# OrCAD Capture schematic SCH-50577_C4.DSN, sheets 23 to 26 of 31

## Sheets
23 25 MCU-Link: size D
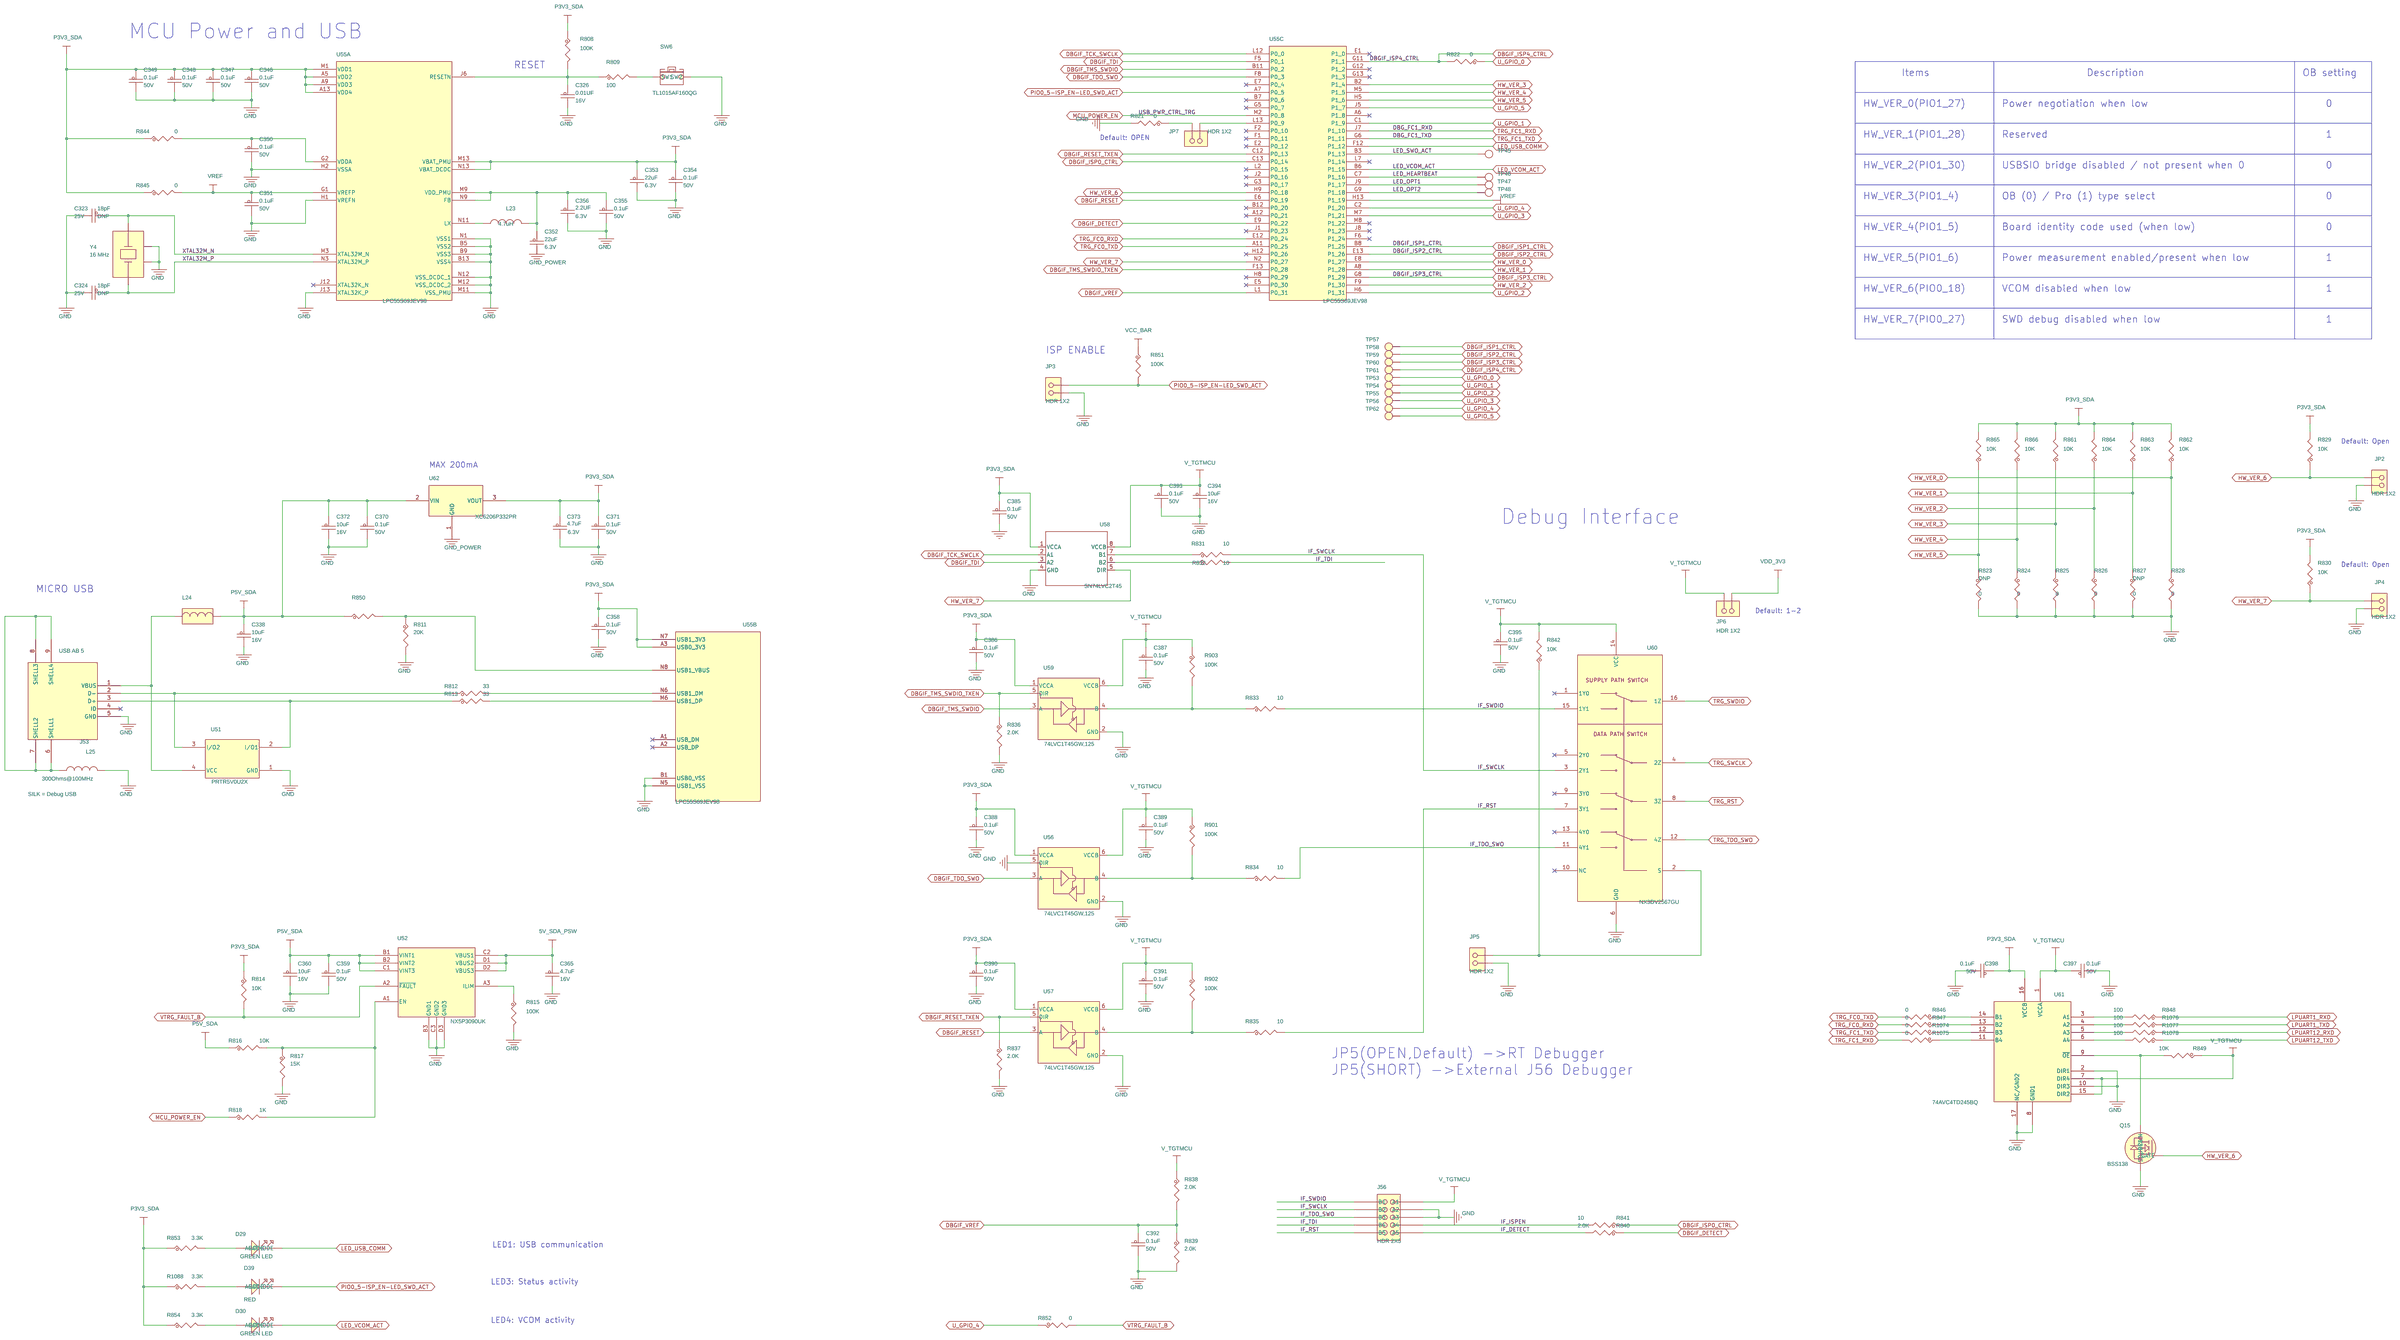
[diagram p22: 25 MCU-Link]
24 27 Audio Extension: size C
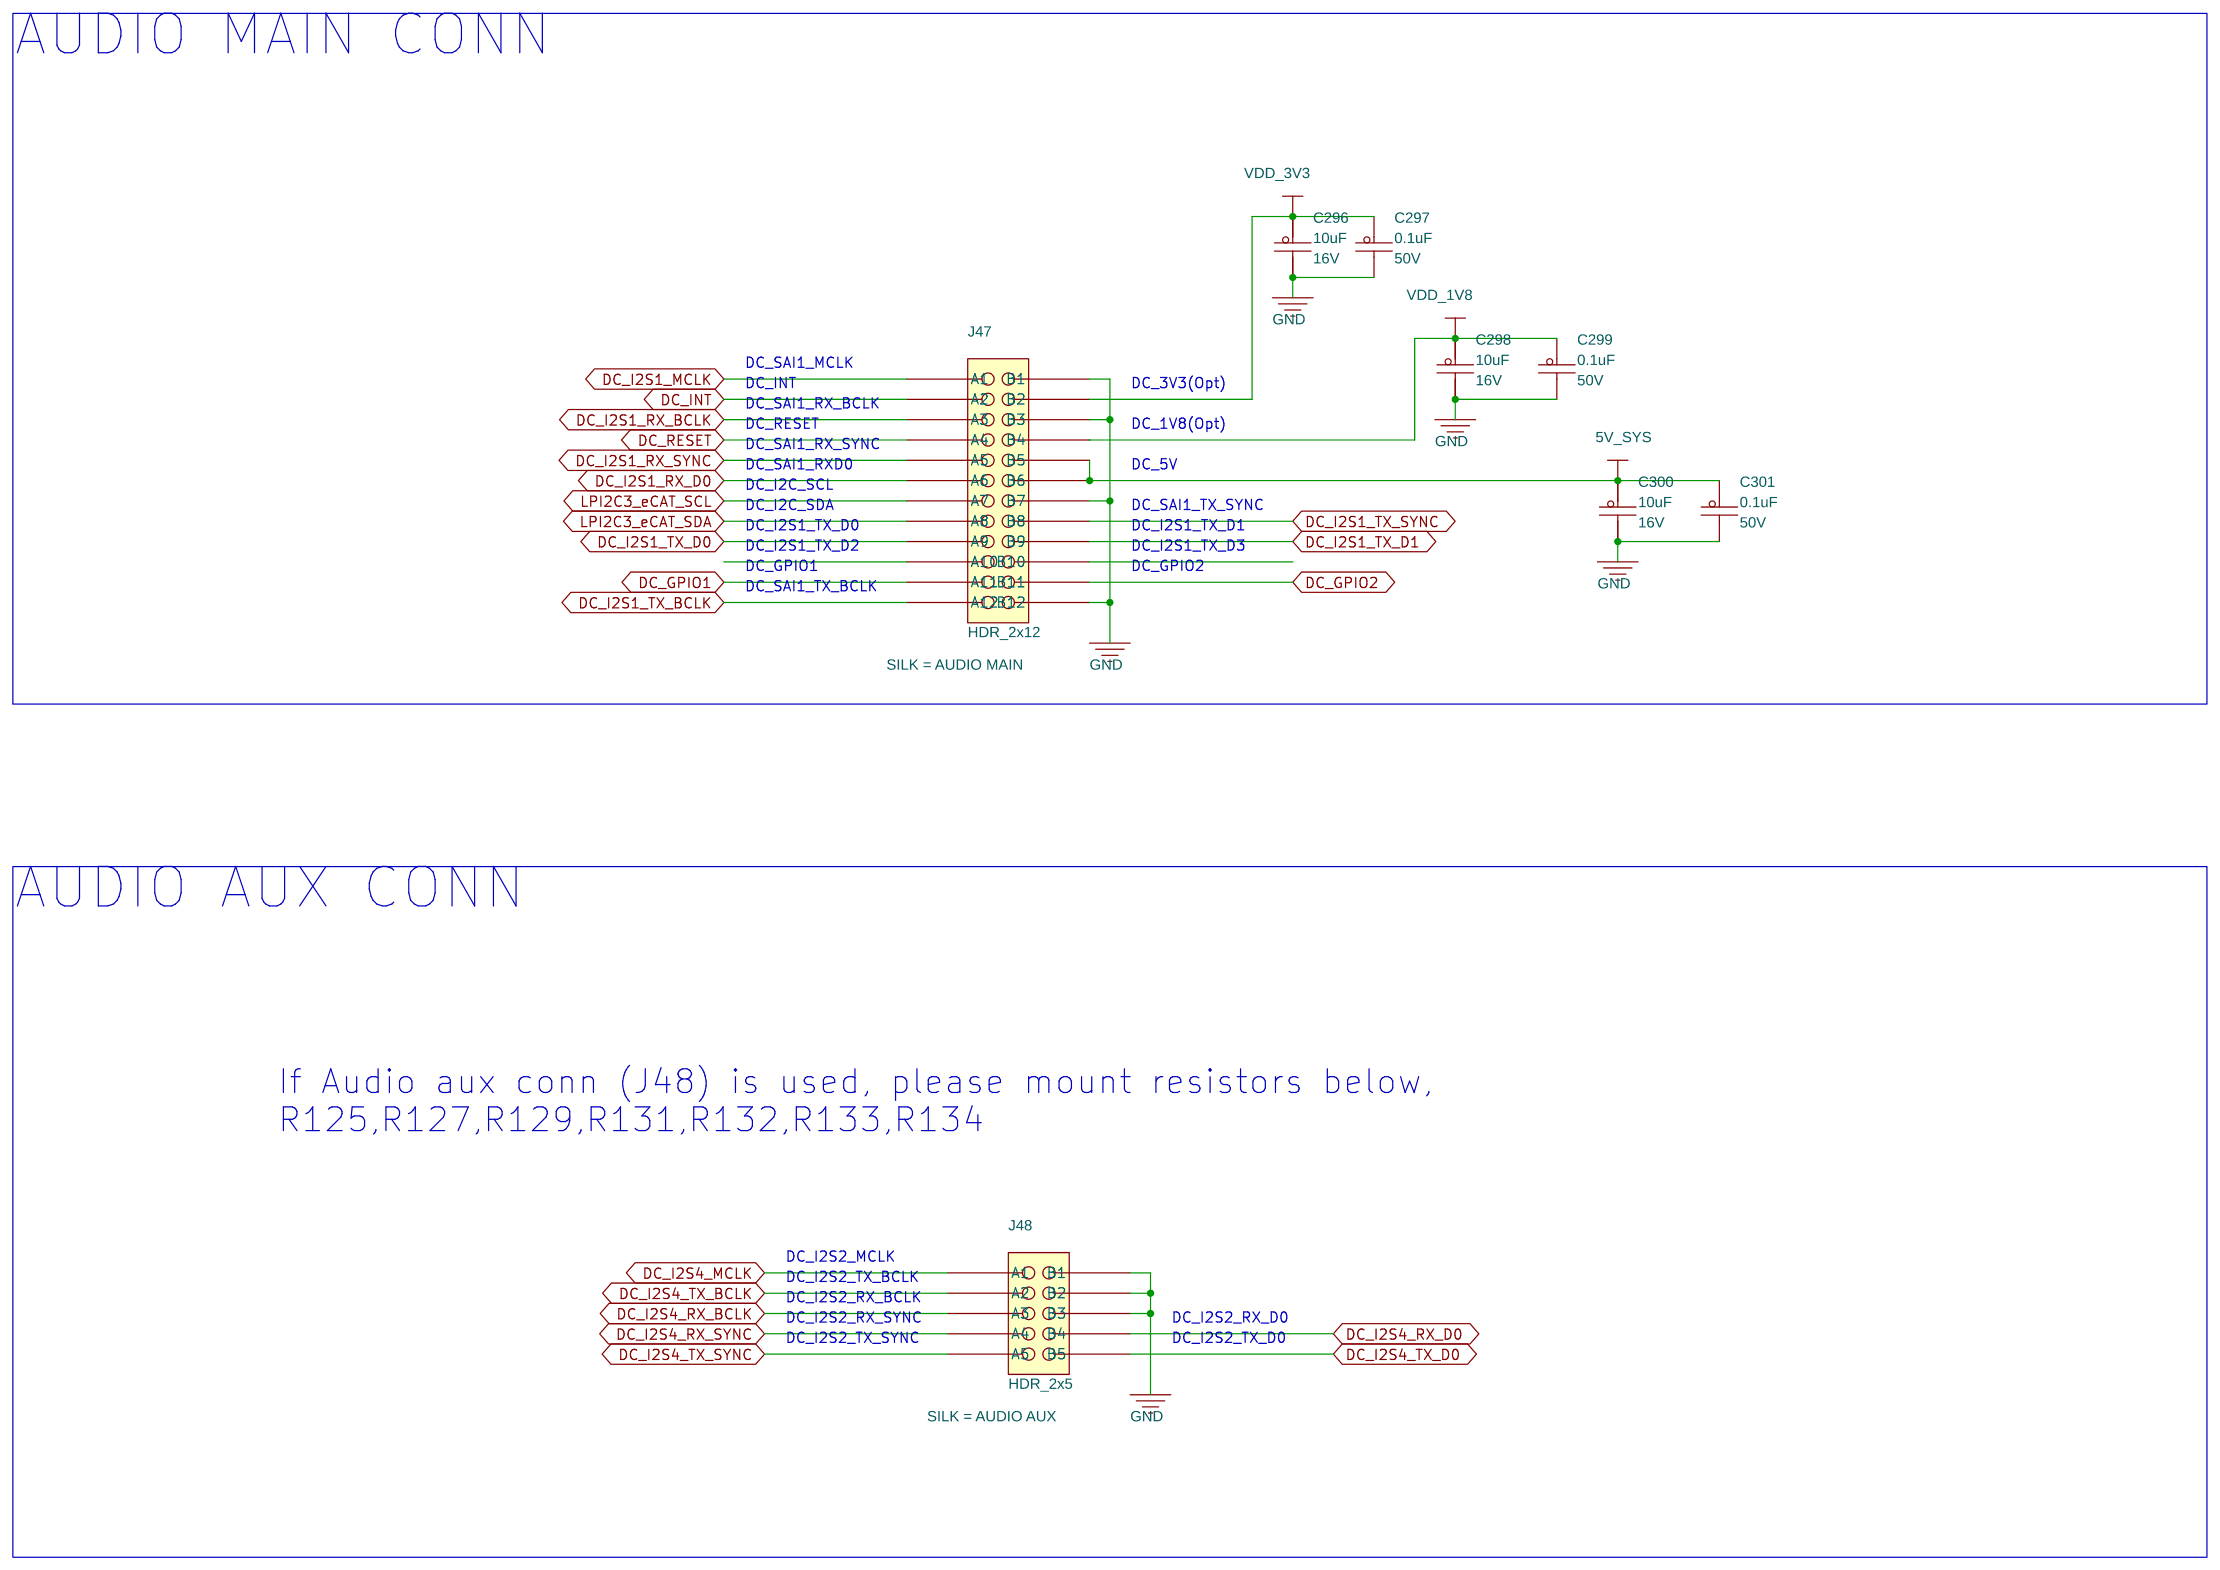
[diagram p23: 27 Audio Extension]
25 28 SINC&I3C: size C
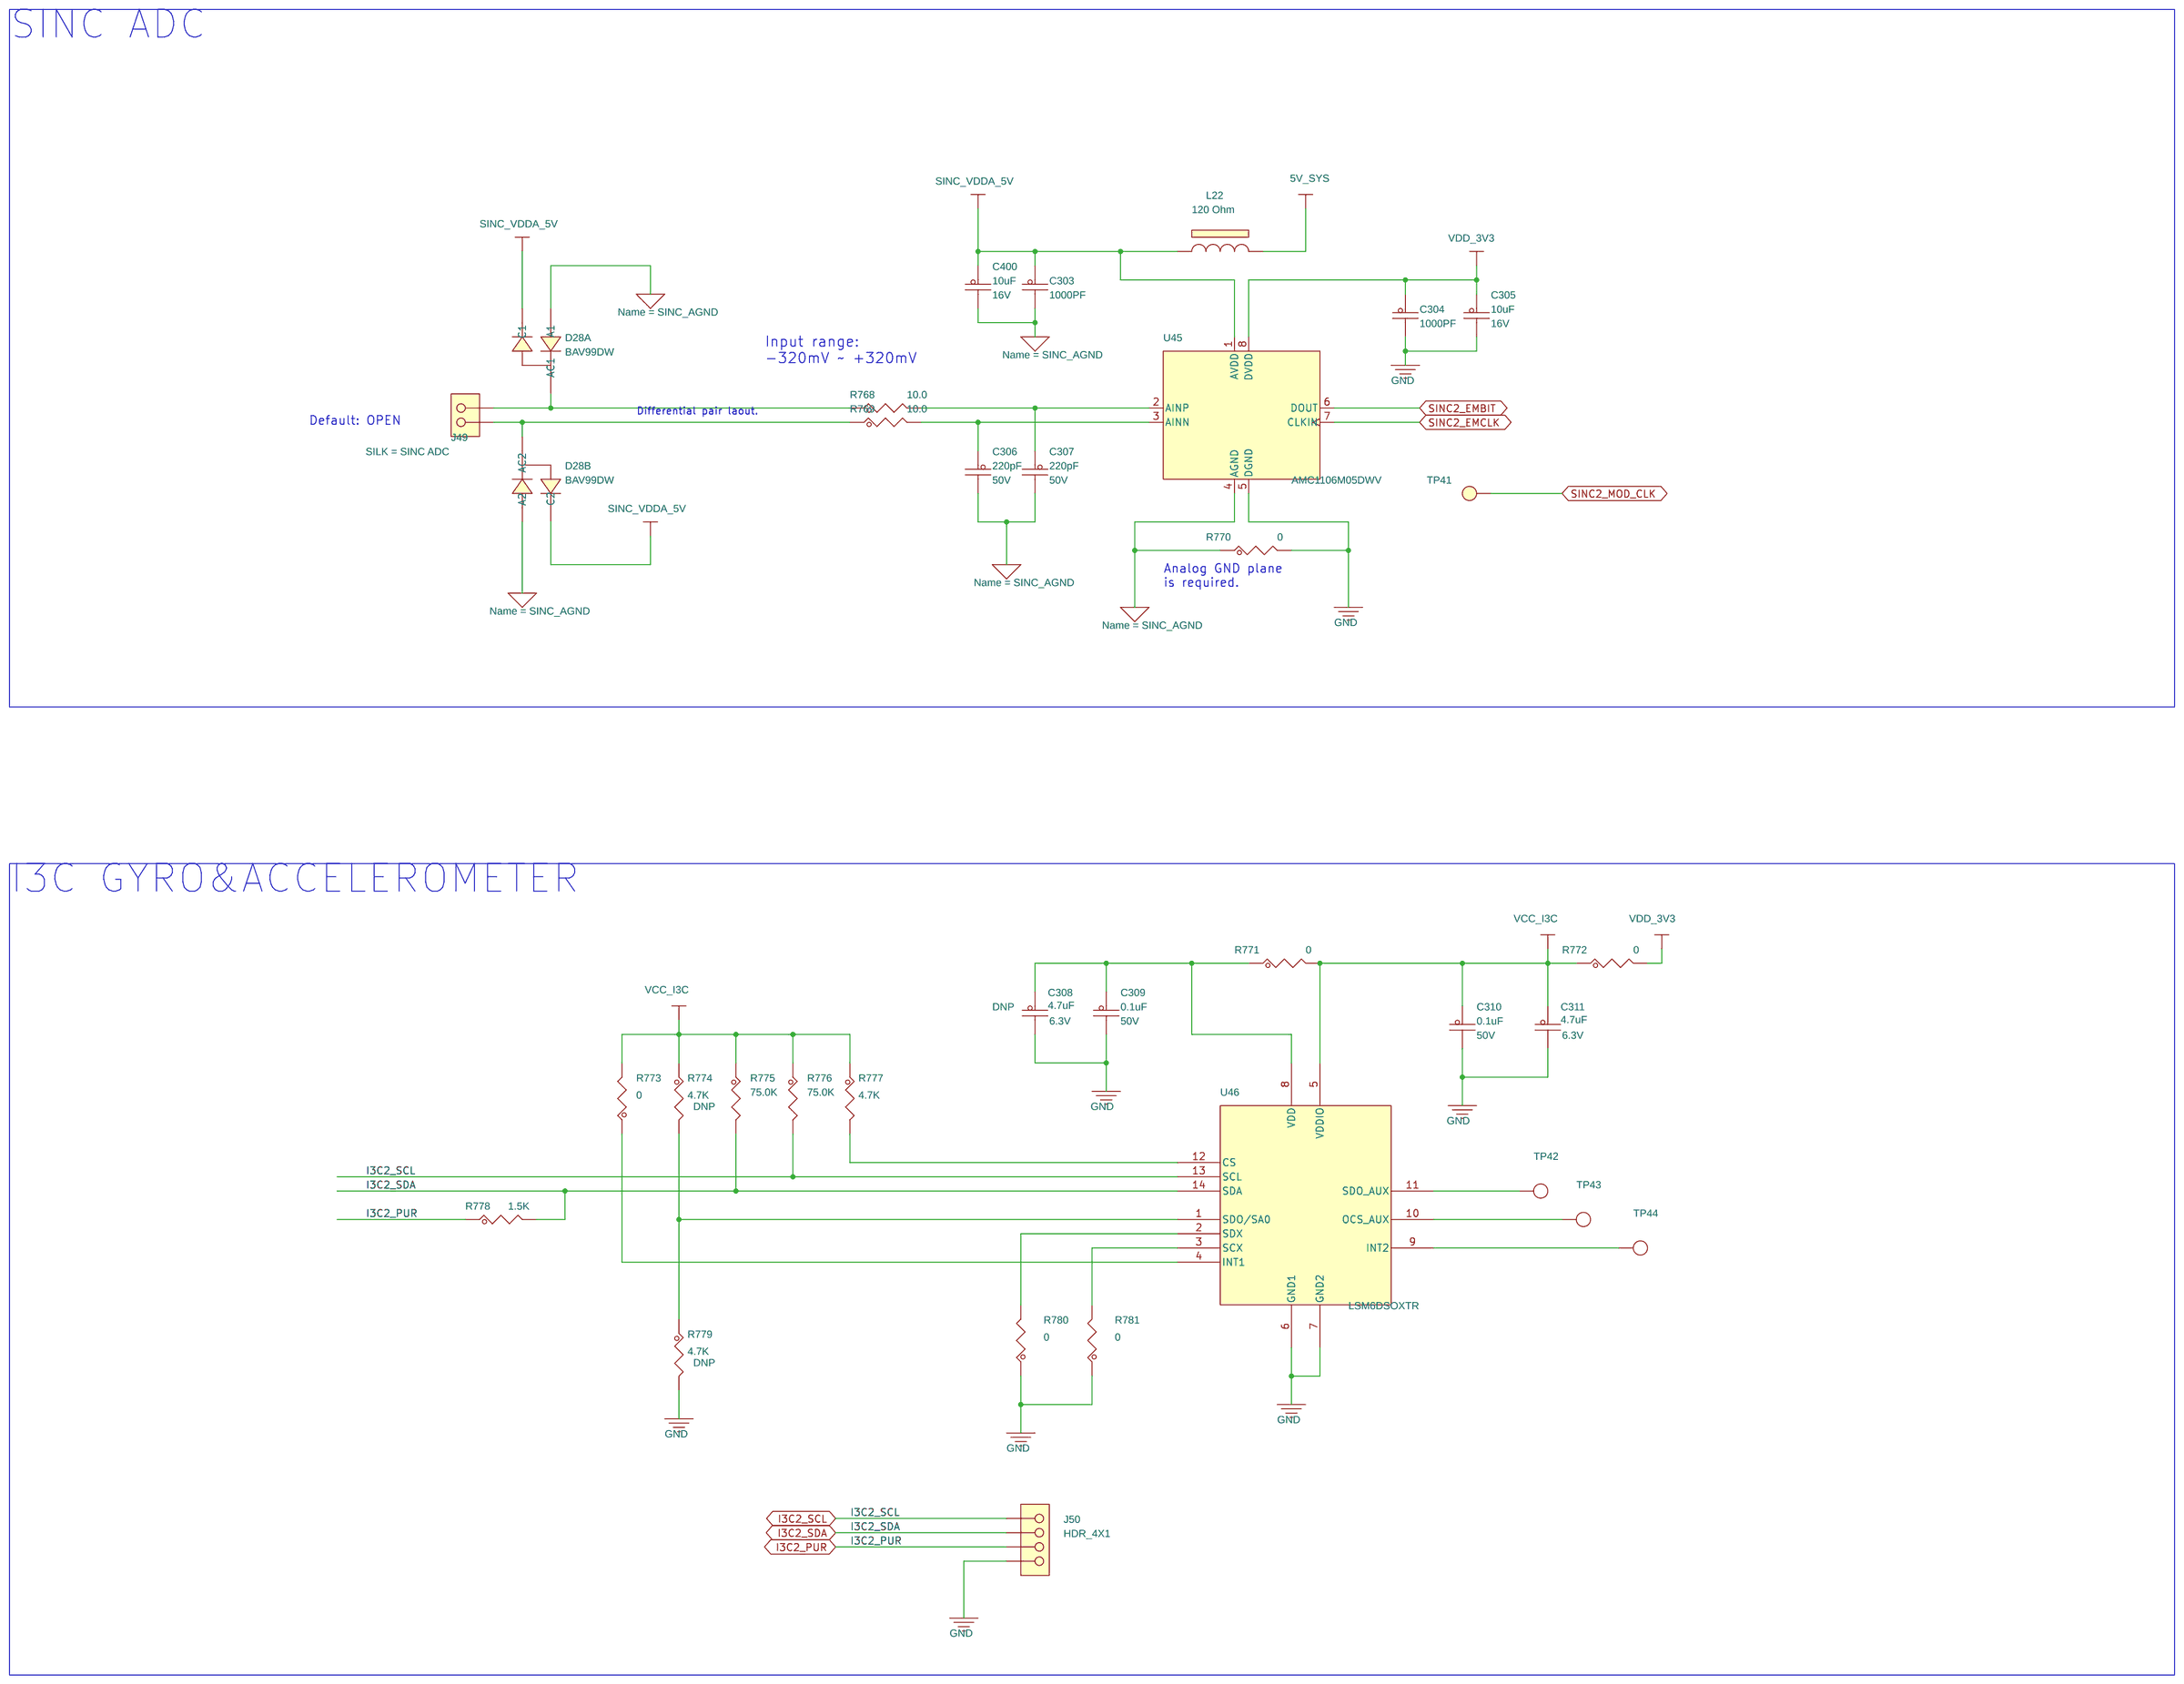
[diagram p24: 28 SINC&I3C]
26 30 MISC: size C
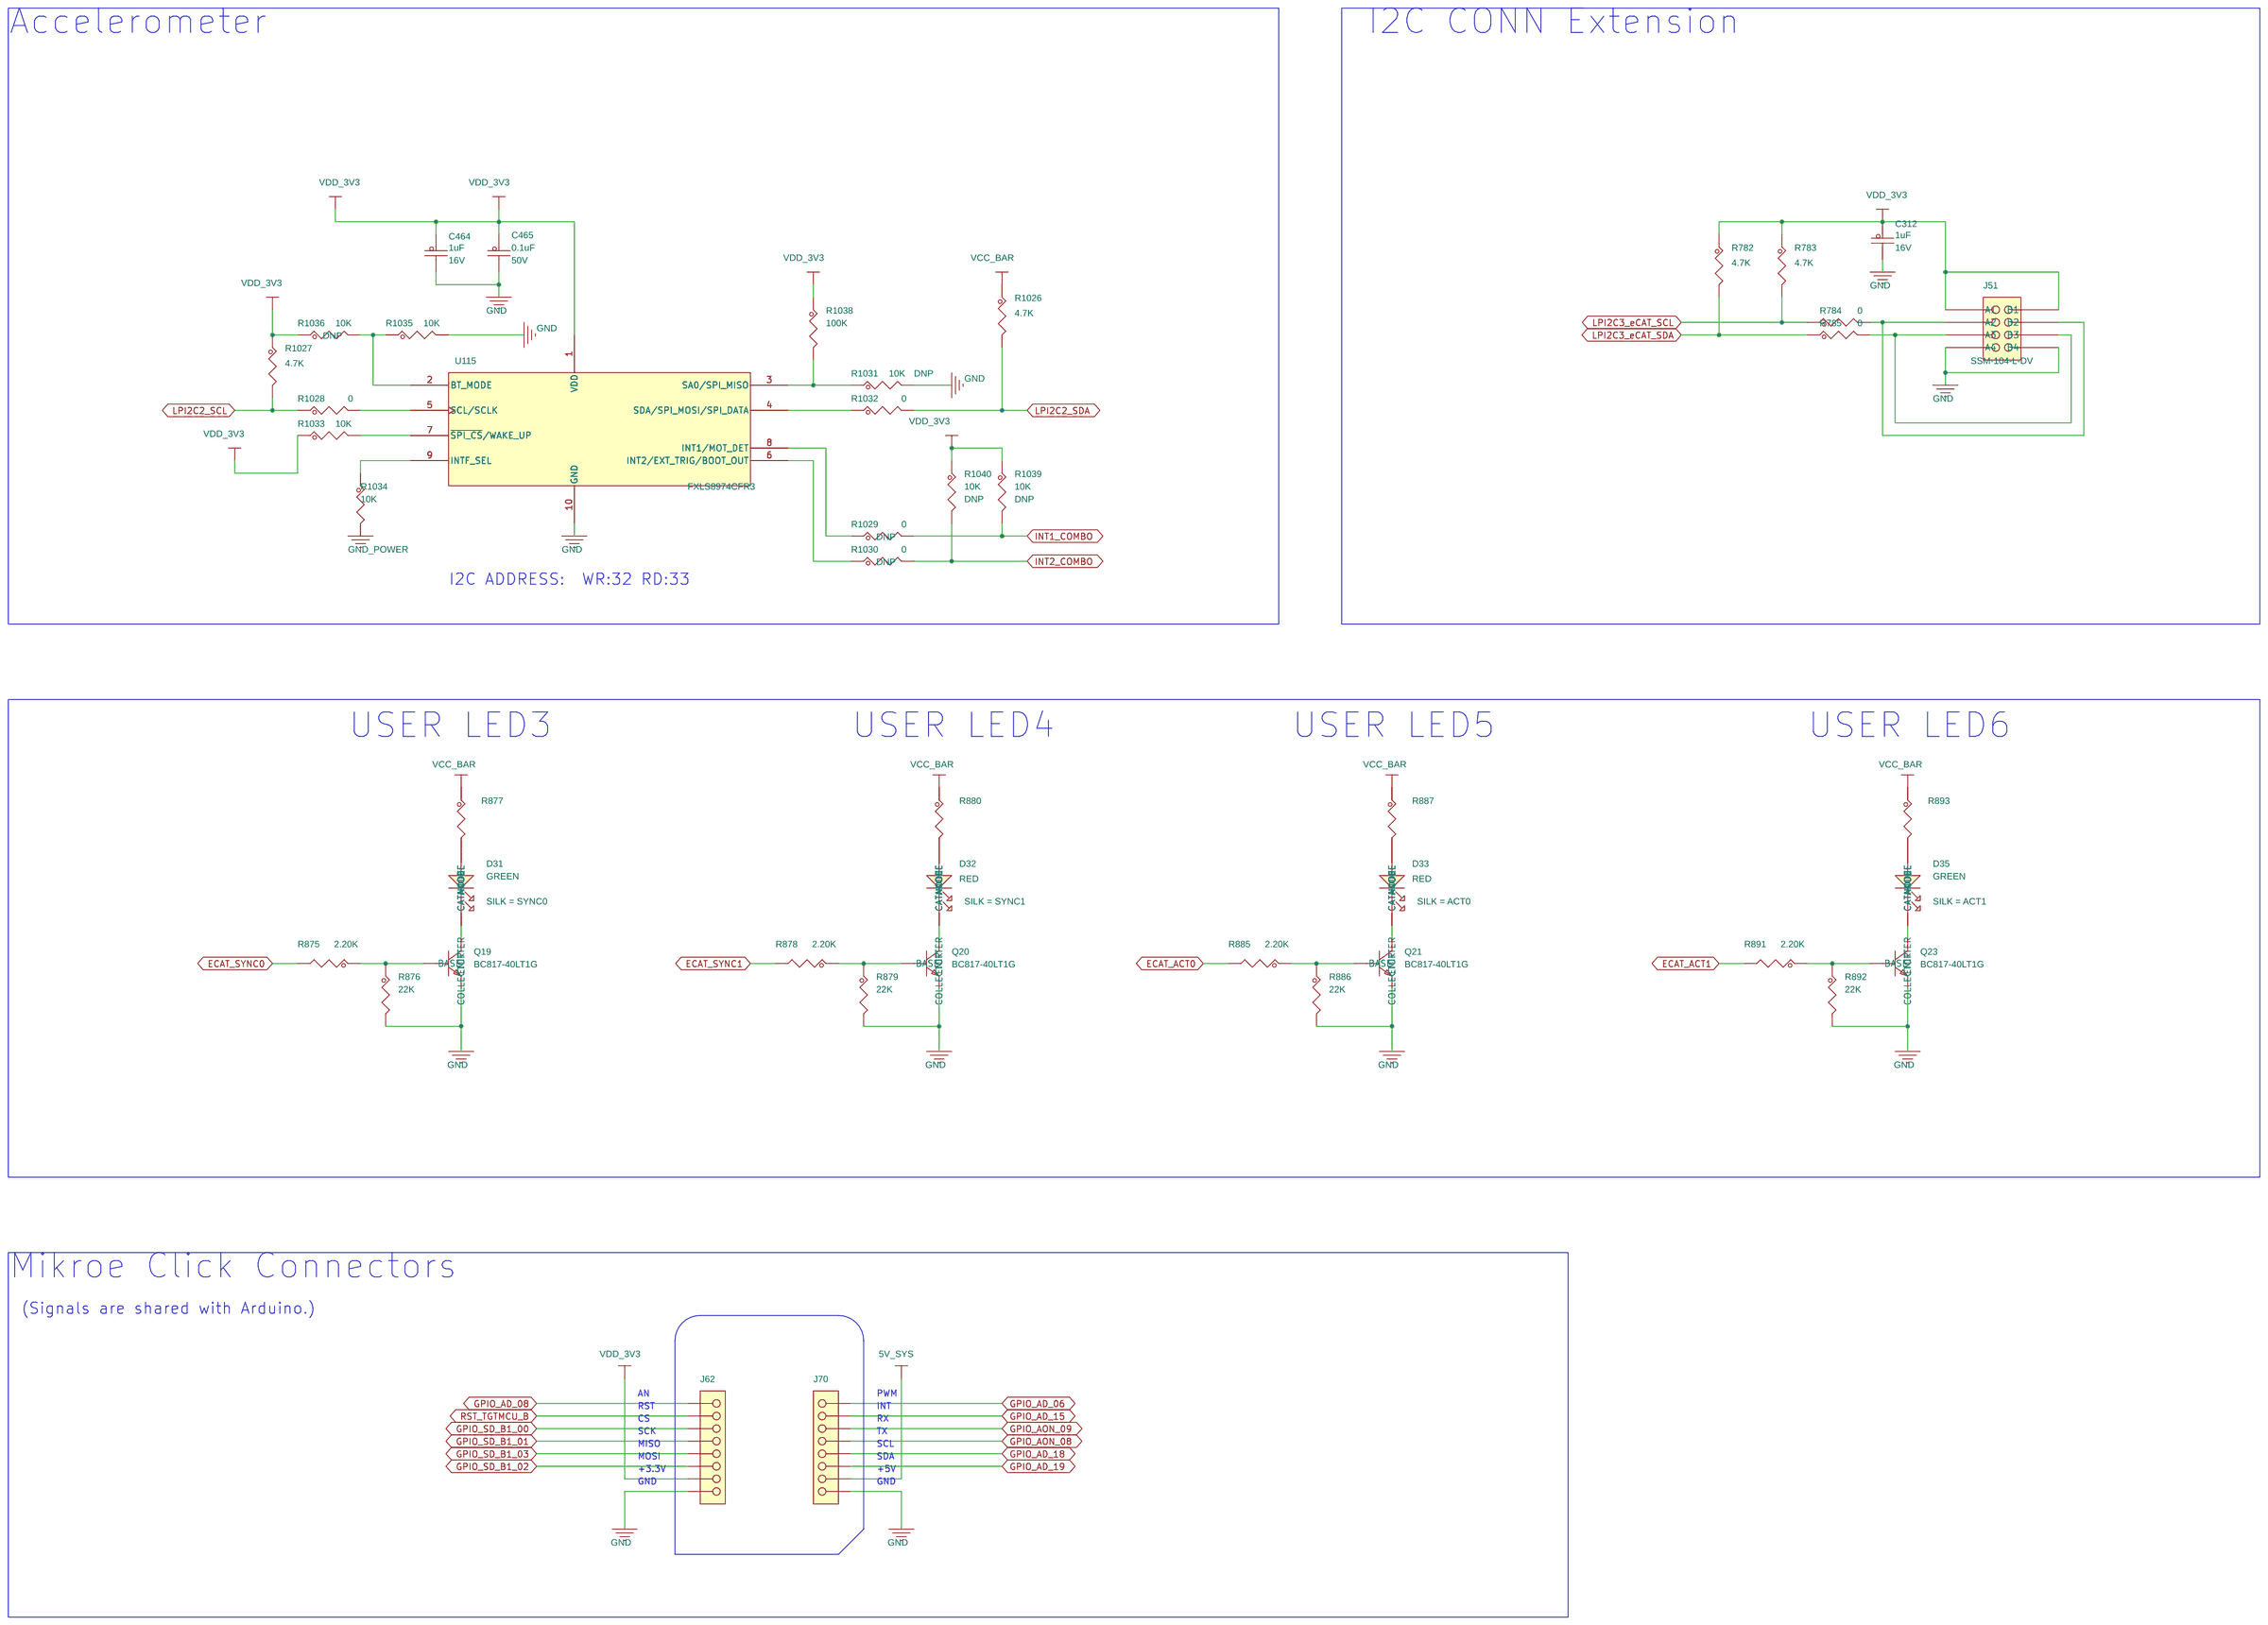
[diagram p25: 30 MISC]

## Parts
sheet 25 MCU-Link
C323  18pF  [0402_CC]
C324  18pF  [0402_CC]
C326  0.01UF  [0402_CC]
C338  10uF  [CC0603_OV]
C346  0.1uF  [0402_CC]
C347  0.1uF  [0402_CC]
C348  0.1uF  [0402_CC]
C349  0.1uF  [0402_CC]
C350  0.1uF  [0402_CC]
C351  0.1uF  [0402_CC]
C352  22uF  [CC0603_OV]
C353  22uF  [CC0603_OV]
C354  0.1uF  [0402_CC]
C355  0.1uF  [0402_CC]
C356  2.2UF  [0402_CC]
C358  0.1uF  [0402_CC]
C359  0.1uF  [0402_CC]
C360  10uF  [CC0603_OV]
C365  4.7uF  [CC0603_OV]
C370  0.1uF  [0402_CC]
C371  0.1uF  [0402_CC]
C372  10uF  [CC0603_OV]
C373  4.7uF  [cc0402_tol0p15]
C385  0.1uF  [0402_CC]
C386  0.1uF  [0402_CC]
C387  0.1uF  [0402_CC]
C388  0.1uF  [0402_CC]
C389  0.1uF  [0402_CC]
C390  0.1uF  [0402_CC]
C391  0.1uF  [0402_CC]
C392  0.1uF  [0402_CC]
C393  0.1uF  [0402_CC]
C394  10uF  [CC0603_OV]
C395  0.1uF  [0402_CC]
C397  0.1uF  [0402_CC]
C398  0.1uF  [0402_CC]
D29  GREEN LED  [LED_0603]
D30  GREEN LED  [LED_0603]
D39  RED  [LED_0603]
J53  USB AB 5  [con9_microAB_usb_shell_th]
J56  HDR 2X5  [con2x5_50_th_a]
JP2  HDR 1X2  [HDR102]
JP3  HDR 1X2  [HDR102]
JP4  HDR 1X2  [HDR102]
JP5  HDR 1X2  [HDR102]
JP6  HDR 1X2  [HDR102]
JP7  HDR 1X2  [HDR102]
L23  4.7uH  [IND_0805]
L24  330 OHM  [IND_0805]
L25  300Ohms@100MHz  [ind_1p8x1mm_sm]
Q15  BSS138  [sot23_a]
R808  100K  [0402_CC]
R809  100  [0402_CC]
R811  20K  [0402_CC]
R812  33  [0402_CC]
R813  33  [0402_CC]
R814  10K  [0402_CC]
R815  100K  [0402_CC]
R816  10K  [0402_CC]
R817  15K  [0402_CC]
R818  1K  [0402_CC]
R821  0  [0402_CC]
R822  0  [0402_CC]
R823  0  [0402_CC]
R824  0  [0402_CC]
R825  0  [0402_CC]
R826  0  [0402_CC]
R827  0  [0402_CC]
R828  0  [0402_CC]
R829  10K  [0402_CC]
R830  10K  [0402_CC]
R831  10  [0402_CC]
R832  10  [0402_CC]
R833  10  [0402_CC]
R834  10  [0402_CC]
R835  10  [0402_CC]
R836  2.0K  [0402_CC]
R837  2.0K  [0402_CC]
R838  2.0K  [0402_CC]
R839  2.0K  [0402_CC]
R840  2.0K  [0402_CC]
R841  10  [0402_CC]
R842  10K  [0402_CC]
R844  0  [0402_CC]
R845  0  [0402_CC]
R846  0  [0402_CC]
R847  0  [0402_CC]
R848  100  [0402_CC]
R849  10K  [0402_CC]
R850  10K  [0402_CC]
R851  100K  [0402_CC]
R852  0  [0402_CC]
R853  3.3K  [0402_CC]
R854  3.3K  [0402_CC]
R861  10K  [0402_CC]
R862  10K  [0402_CC]
R863  10K  [0402_CC]
R864  10K  [0402_CC]
R865  10K  [0402_CC]
R866  10K  [0402_CC]
R901  100K  [0402_CC]
R902  100K  [0402_CC]
R903  100K  [0402_CC]
R1074  0  [0402_CC]
R1075  0  [0402_CC]
R1076  100  [0402_CC]
R1077  100  [0402_CC]
R1078  100  [0402_CC]
R1088  3.3K  [0402_CC]
SW6  TL1015AF160QG  [sw2_spst_4x3_sm_f]
TP45  TPAD_030  [TPAD_030]
TP46  TPAD_030  [TPAD_030]
TP47  TPAD_030  [TPAD_030]
TP48  TPAD_030  [TPAD_030]
TP53  TP_35MIL  [testpoint_35mil]
TP54  TP_35MIL  [testpoint_35mil]
TP55  TP_35MIL  [testpoint_35mil]
TP56  TP_35MIL  [testpoint_35mil]
TP57  TP_35MIL  [testpoint_35mil]
TP58  TP_35MIL  [testpoint_35mil]
TP59  TP_35MIL  [testpoint_35mil]
TP60  TP_35MIL  [testpoint_35mil]
TP61  TP_35MIL  [testpoint_35mil]
TP62  TP_35MIL  [testpoint_35mil]
U51  PRTR5V0U2X  [SOT143B]
U52  NX5P3090UK  [wlcsp12_0p4_1p38x1p68mm_smdp]
U55  LPC55S69JEV98  [bga98_0p5_7x7]  (sections A,B,C)
U56  74LVC1T45GW,125  [SOT-363_0P65_SMT]
U57  74LVC1T45GW,125  [SOT-363_0P65_SMT]
U58  SN74LVC2T45  [SSOP8_DCU]
U59  74LVC1T45GW,125  [SOT-363_0P65_SMT]
U60  NX3DV2567GU  [pqfn16_0p4_2p65x1p85]
U61  74AVC4TD245BQ  [dhvqfn16_0p5_3p6x2p6]
U62  XC6206P332PR  [sot89_123_a]
Y4  16 MHz  [xtlosc4_2p6x2p1mm_sm]
sheet 27 Audio Extension
C296  10uF  [CC0603_OV]
C297  0.1uF  [0402_CC]
C298  10uF  [CC0603_OV]
C299  0.1uF  [0402_CC]
C300  10uF  [CC0603_OV]
C301  0.1uF  [0402_CC]
J47  HDR_2x12  [hdr2x12_2mm_th]
J48  HDR_2x5  [hdr2x5_2mm_th]
sheet 28 SINC&I3C
C303  1000PF  [0402_CC]
C304  1000PF  [0402_CC]
C305  10uF  [CC0603_OV]
C306  220pF  [0402_CC]
C307  220pF  [0402_CC]
C308  4.7uF  [cc0402_tol0p15]
C309  0.1uF  [0402_CC]
C310  0.1uF  [0402_CC]
C311  4.7uF  [cc0402_tol0p15]
C400  10uF  [CC0603_OV]
D28  BAV99DW  [sc70-6]  (sections A,B)
J49  HDR 1X2  [HDR102]
J50  HDR_4X1  [HDR104_STAG_TSM_SM]
L22  120 Ohm  [0402_CC]
R768  10.0  [0402_CC]
R769  10.0  [0402_CC]
R770  0  [0402_CC]
R771  0  [0402_CC]
R772  0  [0402_CC]
R773  0  [0402_CC]
R774  4.7K  [0402_CC]
R775  75.0K  [RC0402_25]
R776  75.0K  [RC0402_25]
R777  4.7K  [0402_CC]
R778  1.5K  [RC0402_25]
R779  4.7K  [0402_CC]
R780  0  [0402_CC]
R781  0  [0402_CC]
TP41  TP_35MIL  [testpoint_35mil]
TP42  TEST POINT  [tp_th_018]
TP43  TEST POINT  [tp_th_018]
TP44  TEST POINT  [tp_th_018]
U45  AMC1106M05DWV  [soic8_1p27_7p6x5p95mm]
U46  LSM6DSOXTR  [lga14_0p5_3x2p5]
sheet 30 MISC
C312  1uF  [0402_CC]
C464  1uF  [0402_CC]
C465  0.1uF  [0402_CC]
D31  GREEN  [LED_0603]
D32  RED  [LED_0603]
D33  RED  [LED_0603]
D35  GREEN  [LED_0603]
J51  SSM-104-L-DV  [con_2x4_skt_100_sm]
J62  SKT_1X8  [con_1x8_skt_2p54_th]
J70  SKT_1X8  [con_1x8_skt_2p54_th]
Q19  BC817-40LT1G  [SOT23]
Q20  BC817-40LT1G  [SOT23]
Q21  BC817-40LT1G  [SOT23]
Q23  BC817-40LT1G  [SOT23]
R782  4.7K  [0402_CC]
R783  4.7K  [0402_CC]
R784  0  [0402_CC]
R785  0  [0402_CC]
R875  2.20K  [RC0603_OV]
R876  22K  [0402_CC]
R877  220  [RC0603_OV]
R878  2.20K  [RC0603_OV]
R879  22K  [0402_CC]
R880  220  [RC0603_OV]
R885  2.20K  [RC0603_OV]
R886  22K  [0402_CC]
R887  220  [RC0603_OV]
R891  2.20K  [RC0603_OV]
R892  22K  [0402_CC]
R893  220  [RC0603_OV]
R1026  4.7K  [0402_CC]
R1027  4.7K  [0402_CC]
R1028  0  [0402_CC]
R1029  0  [0402_CC]
R1030  0  [0402_CC]
R1031  10K  [0402_CC]
R1032  0  [0402_CC]
R1033  10K  [0402_CC]
R1034  10K  [0402_CC]
R1035  10K  [0402_CC]
R1036  10K  [0402_CC]
R1038  100K  [0402_CC]
R1039  10K  [0402_CC]
R1040  10K  [0402_CC]
U115  FXLS8974CFR3  [DFN_10_0P4_2X2]

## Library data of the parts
C323 C324 = CAP_NP: CAP CER 18pF 25V 5% C0G 0402; AGILE_PN: 150-78760; ASSY_OPT: DNP; CAD_APPROVED: Yes; FPLIST: CC0402_25,CC0402_HD,0402_CC; HEIGHT: 0.56MM; MFG_NAME01: AVX; MFG_PN01: 04023A180JAT2A; ROHS: Yes; TOL: 5%; Tolerance: 5%; VOLTAGE: 25V
C326 = CAP_NP: CAP CER 0.01UF 16V 20% X7R 0402; AGILE_PN: 150-30082; CAD_APPROVED: Yes; FPLIST: CC0402_25,CC0402_HD,0402_CC; HEIGHT: 0.56MM; MFG_NAME01: AVX; MFG_PN01: 0402YC103MAT2A; Package Size: 0402; ROHS: Yes; TOL: 20%; Tolerance: 20%; VOLTAGE: 16V
C296 C298 C300 C305 C338 C360 C372 C394 C400 = CAP_NP: CAP CER 10uF 16V 20% X6S AEC-Q200 0603; AGILE_PN: 150-80530; CAD_APPROVED: Yes; FPLIST: CC0603_OV,CC0603,0603_CC_NSP; HEIGHT: 1MM; MFG_NAME01: MURATA; MFG_PN01: GRT188C81C106ME13D; Package Size: 0603; ROHS: Yes; Temp Range: -55°C to 105°C; Tolerance: 10%; VOLTAGE: 16V
C297 C299 C301 C309 C310 C346-C351 C354 C355 C358 C359 C370 C371 C385-C393 C395 C397 C398 C465 = CAP_NP: CAP CER 0.1uF 50V 10% X7R AEC-Q200 0402; AGILE_PN: 150-79461; CAD_APPROVED: Yes; FPLIST: CC0402_25,CC0402_HD,0402_CC,CC0402_18,capc0402_l; HEIGHT: 0.55MM; MFG_NAME01: MURATA; MFG_PN01: GCM155R71H104KE02D; Package Size: 0402; ROHS: Yes; Tolerance: 10%; VOLTAGE: 50V
C352 C353 = CAP_NP: CAP CER 22uF 6.3V 20% X6S 0603; AGILE_PN: 150-79717; CAD_APPROVED: Yes; FPLIST: CC0603_OV,CC0603,0603_CC_NSP; HEIGHT: 1MM; MFG_NAME01: MURATA; MFG_PN01: GRM188C80J226ME15D; Package Size: 0603; Package Type: 180mm ReelPAPER W8P4; ROHS: Yes; Tolerance: 20%; VOLTAGE: 6.3V
C356 = CAP_NP: CAP CER 2.2UF 6.3V 10% X6S 0402; AGILE_PN: 150-80139; CAD_APPROVED: Yes; FPLIST: CC0402_25,CC0402_HD,0402_CC,capc0402_l; HEIGHT: 0.55MM; MFG_NAME01: MURATA; MFG_PN01: GRM155C80J225KE95D; ROHS: Yes; Temp Range: -55 to 105&#8451;; VOLTAGE: 6.3V
C365 = CAP_NP: CAP CER 4.7uF 16V 10% X7R 0603; AGILE_PN: 150-80123; CAD_APPROVED: Yes; FPLIST: CC0603_OV,CC0603,0603_cc_tol,cc0603_0805_nsp; HEIGHT: 1MM; MFG_NAME01: MURATA; MFG_PN01: GRM188Z71C475KE21; Package Size: 0603; ROHS: Yes; Temp Range: -55°C ~ 125°C; Tolerance: 10%; VOLTAGE: 16V
C311 C373 = CAP_NP: CAP CER 4.7uF 6.3V 20% X6S 0402; AGILE_PN: 150-81296; CAD_APPROVED: Yes; FPLIST: cc0402_tol0p15,cc0402_tol0p15_ov,cc0402_25_tol0p2,0402_cc_nsp; HEIGHT: 0.65MM; MFG_NAME01: MURATA; MFG_PN01: GRM155C80J475MEAA; Package Size: 0402 (1005 Metric); Package Type: SMD/SMT; ROHS: Yes; Rated Voltage: 6.3V; Temp Range: -55°C to +105°C; Tolerance: 20%; VOLTAGE: 6.3V
D29 D30 = LED: LED GRN SGL 20MA SMT 0603; AGILE_PN: 370-75904; CAD_APPROVED: Yes; HEIGHT: 0.65MM; MFG_NAME01: VISHAY INTERTECHNOLOGY; MFG_PN01: TLMG1100-GS08; VOLTAGE: 3V
D39 = LED: LED ULTRA BRIGHT RED SGL 30MA 0603; AGILE_PN: 370-75079; CAD_APPROVED: Yes; HEIGHT: 0.9MM; MFG_NAME01: LITE ON; MFG_PN01: LTST-C190KRKT; ROHS: Yes; Rated Voltage: 2V; Temp Range: -30° C to + 85° C; Temp_Range: -30° C to + 85° C; VOLTAGE: 2V
J53 = MICRO_USB_CONN_9PIN: CON 5 USB MICRO-AB RA SKT SMT 0.65MM SP AU; 3D_Mechanical_Footprint_File: ftp://fcl.am.freescale.net/ALLEGRO/step/con9_microAB_usb_shell_th.STEP; AGILE_PN: 211-78692; CAD_APPROVED: Yes; HEIGHT: 2.8MM; MFG_NAME01: HIROSE; MFG_PN01: ZX62D-AB-5P8(30); ROHS: Yes; SILK: Debug USB
J56 = CONN_HDR_5X2: HDR 2X5 TH 50MIL CTR 222H AU 90L; 3D_Mechanical_Footprint_File: ftp://fcl.am.freescale.net/ALLEGRO/step/con2x5_50_th_a.STEP; AGILE_PN: 210-82391; CAD_APPROVED: Yes; HEIGHT: 5.65MM; MFG_NAME01: WURTH ELEKTRONIK EISOS GMBH & CO. KG (ELECTRONIC & ELECTROMEHANICAL COMP); MFG_PN01: 62201021121; ROHS: Yes; Temp Range: -40C to +105C
JP2-JP5 JP7 = CONN_HDR_2X1: HDR 1X2 TH 100MIL SP 339H AU 98L; AGILE_PN: 210-81490; CAD_APPROVED: Yes; FPLIST: HDR102,SH_HDR102_BOTTOM; HEIGHT: 8.59MM; MFG_NAME01: ANYTRONIC CORPORATION LIMITED; MFG_PN01: 0901S0202011N9T-31RF; ROHS: Yes; Temp Range: -55°C to +105°C; Temp_Range: -55°C to +105°C
JP6 = CONN_HDR_2X1: HDR 1X2 TH 100MIL SP 339H AU 98L; AGILE_PN: 210-81490; CAD_APPROVED: Yes; FPLIST: HDR102,SH_HDR102_BOTTOM; HEIGHT: 8.59MM; Jumper(Default): 1-2; MFG_NAME01: ANYTRONIC CORPORATION LIMITED; MFG_PN01: 0901S0202011N9T-31RF; ROHS: Yes; Temp Range: -55°C to +105°C; Temp_Range: -55°C to +105°C
L23 = INDUCTOR: IND -- 4.7uH@1MHZ 800mA 20% 0805; AGILE_PN: 180-79181; CAD_APPROVED: yes; HEIGHT: 1MM; MFG_NAME01: Murata Electronics; MFG_PN01: LQM21PN4R7MGRD; Package Size: 0805 (2012 Metric); ROHS: Yes
L24 = BEAD: IND FER BEAD 330OHM@100MHZ 2.5A -- SMT; 3D_Mechanical_Footprint_File: ftp://fcl.am.freescale.net/ALLEGRO/step/ind_0805.STEP; AGILE_PN: 180-30021; CAD_APPROVED: YES; HEIGHT: 1.05 MM; MFG_NAME01: TDK; MFG_PN01: MPZ2012S331AT000; PART_TYPE: FERRITE; ROHS: Yes; Temp Range: -55°C to +125°C; Tolerance: 25%
L25 = INDUCTOR: IND FER BEAD 300Ohms@100MHz 2A 25% 0603; AGILE_PN: 180-78959; CAD_APPROVED: Yes; HEIGHT: 1MM; MFG_NAME01: WURTH ELEKTRONIK EISOS GMBH & CO. KG (ELECTRONIC & ELECTROMEHANICAL COMP); MFG_PN01: 742792641; Package Size: 0603; ROHS: Yes; Temp Range: -55°C to 125°C
Q15 = NMOS_3P_A: TRAN NMOS PWR 200mA 50V AEC-Q101 SOT23; AGILE_PN: 480-80247; CAD_APPROVED: Yes; HEIGHT: 1.1MM; MFG_NAME01: DIODES INC; MFG_PN01: BSS138Q-7-F; ROHS: Yes; Temp Range: -55C to +150C
R808 R815 R851 = RES: RES MF 100K 1/16W 5% AEC-Q200 0402; AGILE_PN: 470-82056; CAD_APPROVED: Yes; HEIGHT: 0.4MM; MFG_NAME01: VISHAY INTERTECHNOLOGY; MFG_PN01: CRCW0402100KJNED; ROHS: Yes; Temp Range: -55C to +155C; Tolerance: 5%; VOLTAGE: 50V
R809 = RES: RES MF 100 OHM 1/16W 5% 0402; AGILE_PN: 470-82143; CAD_APPROVED: Yes; HEIGHT: 0.45MM; MFG_NAME01: YAGEO AMERICA; MFG_PN01: RC0402JR-07100RL; ROHS: Yes; Temp Range: -55°C to +155°C; Tolerance: 5%
R811 = RES: RES MF 20K 1/16W 5% 0402; AGILE_PN: 470-76086; CAD_APPROVED: Yes; HEIGHT: 0.4 MM; MFG_NAME01: YAGEO AMERICA; MFG_PN01: RC0402JR-0720KL; ROHS: Yes; Tolerance: 5%
R812 R813 = RES: RES MF 33 OHM 1/16W 5% 0402; AGILE_PN: 470-75634; CAD_APPROVED: Yes; HEIGHT: 0.41mm; MFG_NAME01: SMEC; MFG_PN01: RC73L2Z330JTF; ROHS: Yes; Tolerance: 5%
R814 R816 R829 R830 R842 R849 R861-R866 = RES: RES MF 10K 1/16W 5% 0402; AGILE_PN: 470-75557; CAD_APPROVED: Yes; HEIGHT: 0.4 MM; MFG_NAME01: VISHAY INTERTECHNOLOGY; MFG_PN01: CRCW040210K0JNED; ROHS: Yes; Tolerance: 5%
R817 = RES: RES MF 15K 1/16W 5% 0402; AGILE_PN: 470-30313; CAD_APPROVED: Yes; FPLIST: RC0402_25,RC0402_HD,0402_CC; HEIGHT: 0.45 MM; MFG_NAME01: VISHAY INTERTECHNOLOGY; MFG_PN01: CRCW040215K0JNED; ROHS: Yes; Tolerance: 5%; VOLTAGE: 1/16W
R818 = RES: RES MF 1.0K 1/16W 5% 0402; AGILE_PN: 470-75555; CAD_APPROVED: Yes; HEIGHT: 0.41mm; MFG_NAME01: VISHAY INTERTECHNOLOGY; MFG_PN01: CRCW04021K00JNED; ROHS: Yes; Tolerance: 5%
R821 R822 R824-R826 R828 R846 R847 R852 R1074 R1075 = RES: RES MF ZERO OHM 1/16W 5% 0402; AGILE_PN: 470-75394; CAD_APPROVED: Yes; FPLIST: RC0402_25,RC0402_HD,RC0402_X2,0402_CC; HEIGHT: 0.45 MM; MFG_NAME01: YAGEO AMERICA; MFG_PN01: RC0402JR-070RL; ROHS: Yes; SIGNAL_MODEL: DEFAULT_RESISTOR_33.000000OHM_2_1; TOL: 5%; Tolerance: 5%; VOLTAGE: 1/16W
R823 R827 = RES: RES MF ZERO OHM 1/16W 5% 0402; AGILE_PN: 470-75394; ASSY_OPT: DNP; CAD_APPROVED: Yes; FPLIST: RC0402_25,RC0402_HD,RC0402_X2,0402_CC; HEIGHT: 0.45 MM; MFG_NAME01: YAGEO AMERICA; MFG_PN01: RC0402JR-070RL; ROHS: Yes; SIGNAL_MODEL: DEFAULT_RESISTOR_33.000000OHM_2_1; TOL: 5%; Tolerance: 5%; VOLTAGE: 1/16W
R831-R835 R841 = RES: RES MF 10 OHM 1/16W 1% AEC-Q200 0402; AGILE_PN: 470-80978; CAD_APPROVED: Yes; FPLIST: RC0402_25,RC0402_HD,0402_CC; HEIGHT: 0.4MM; MFG_NAME01: KOA SPEER; MFG_PN01: RK73H1ETTP10R0F; ROHS: Yes; Temp Range: –55 °C to +155 °C; Tolerance: 1%
R836-R840 = RES: RES MF 2.0K 1/16W 5% 0402; AGILE_PN: 470-75638; CAD_APPROVED: Yes; FPLIST: RC0402_25,RC0402_HD,0402_CC; HEIGHT: 0.45MM; MFG_NAME01: SMEC; MFG_PN01: RC73L2Z202JTF; ROHS: Yes; Tolerance: 5%; VOLTAGE: 1/16W
R770-R773 R780 R781 R844 R845 = RES: RES MF ZERO OHM 1/16W 5% 0402; AGILE_PN: 470-75394; CAD_APPROVED: Yes; FPLIST: RC0402_25,RC0402_HD,RC0402_X2,0402_CC; HEIGHT: 0.45 MM; MFG_NAME01: ROHM; MFG_PN01: MCR01MZPJ000; ROHS: Yes; Tolerance: 5%; VOLTAGE: 1/16W
R848 R1076-R1078 = RES: RES MF 100 OHM 1/16W 5% AEC-Q200 0402; AGILE_PN: 470-80555; CAD_APPROVED: Yes; FPLIST: RC0402_25,RC0402_HD,RC0402_X2,0402_CC; HEIGHT: 0.45mm; MFG_NAME01: VISHAY INTERTECHNOLOGY; MFG_PN01: CRCW0402100RJNED; ROHS: Yes
R850 = RES: RES MF 10K 1/16W 5% 0402; AGILE_PN: 470-75557; CAD_APPROVED: Yes; FPLIST: RC0402_25,RC0402_HD,0402_CC; HEIGHT: 0.4 MM; MFG_NAME01: VISHAY INTERTECHNOLOGY; MFG_PN01: CRCW040210K0JNED; ROHS: Yes; TOL: 5%; Tolerance: 5%
R853 R854 R1088 = RES: RES MF 3.3K 1/16W 5% 0402; AGILE_PN: 470-76064; CAD_APPROVED: Yes; FPLIST: RC0402_25,RC0402_HD,0402_CC; HEIGHT: 0.40 MM; MFG_NAME01: YAGEO AMERICA; MFG_PN01: RC0402JR-073K3L; ROHS: Yes; Tolerance: 5%; VOLTAGE: 1/16W
R901-R903 = RES: RES MF 100K 1/16W 1% 0402; AGILE_PN: 470-76240; CAD_APPROVED: Yes; FPLIST: RC0402_25,RC0402_HD,0402_CC; HEIGHT: 0.4MM; MFG_NAME01: NIC COMPONENTS CORP; MFG_PN01: NRCL04F1003TRF; ROHS: Yes; Tolerance: 1%
SW6 = SW2P_SPST: SW SPST PB 50MA 12V SMT; AGILE_PN: 510-77720; CAD_APPROVED: Yes; FPLIST: sw2_spst_4x3_sm,sw2_spst_4x3_sm_f; HEIGHT: 2.4MM; MFG_NAME01: E SWITCH; ROHS: Yes
TP45-TP48 = TESTLOOP: TEST POINT PAD 30MIL DIA SMT, NO PART TO ORDER; 3D_Mechanical_Footprint_File: ftp://fcl.am.freescale.net/ALLEGRO/step/tpad_030.STEP; AGILE_PN: 211-76642; CAD_APPROVED: Yes; HEIGHT: 0.1MM; MFG_NAME01: NOTACOMPONENT; MFG_PN01: NOTACOMPONENT; ROHS: Yes
TP41 TP53-TP62 = T_POINT_R: TEST POINT PAD .035 SMT, no part to order; AGILE_PN: 510-75618; CAD_APPROVED: Yes; HEIGHT: 0.1MM; ROHS: Yes
U51 = PRTR5V0U2X: IC USB ESD PROTECTION 8KV SOT143; AGILE_PN: 315-76725; CAD_APPROVED: Yes; HEIGHT: 1.1MM; MFG_NAME01: NEXPERIA; MFG_PN01: PRTR5V0U2X,215; ROHS: Yes; Temp Range: -40° C to +85° C; VOLTAGE: 5.0V
U52 = NX5P3090UK_WLCSP12: IC USB PD TYPE C CURRENT LIMITED PWR SW 2.5-5.5V WLCSP12; AGILE_PN: 312-81574; CAD_APPROVED: Yes; HEIGHT: 0.565 MM; MFG_NAME01: NXP SEMICONDUCTORS; MFG_PN01: NX5P3090UK,012; ROHS: Yes
U55 = NIOBE4_MINI_FBGA98: IC MCU ARM FLASH 640KB SRAM 320KB 1.8-3.6V VFBGA 98; AGILE_PN: 344-02410; CAD_APPROVED: Yes; FPLIST: bga98_0p5_7x7,bga98_0p5_7x7_c010s_nsp; HEIGHT: 0.97 MM; MFG_NAME01: NXP SEMICONDUCTORS; ROHS: Yes; Supply Voltage: 1.8-3.6V; Temp Range: -40 to +105C; VOLTAGE: 1.8/3.6V
U56 U57 U59 = 74LVCH1T45_6P: IC XCVR XLATING DUAL 3-STATE 1.2- 5.5V TSSOP6; AGILE_PN: 312-81277; CAD_APPROVED: Yes; HEIGHT: 1.1MM; MFG_NAME01: NEXPERIA; ROHS: Yes; VOLTAGE: 1.2- 5.5V
U58 = SN74LVC2T45DCUT_8P: IC XCVR DUAL BIT 1.65-5.5V VSSOP8; AGILE_PN: 312-80349; CAD_APPROVED: Yes; HEIGHT: 0.9MM; MFG_NAME01: TEXAS INSTRUMENTS; MFG_PN01: SN74LVC2T45DCUT; ROHS: Yes
U60 = NX3DV2567GU_XQFN_16P: IC LIN SW 4PDT 1.4-4.3V XQFN16; AGILE_PN: 315-80822; CAD_APPROVED: Yes; HEIGHT: 0.5 MM; MFG_NAME01: NXP SEMICONDUCTORS; MFG_PN01: NX3DV2567GU,115; ROHS: Yes; VOLTAGE: 1.4-4.3V
U61 = 74AVC4TD245BQ_DHVQFN16: IC DUAL SUPPLY XCVR XLTR 4BIT 0-3.6V DHVQFN16; 3D_Mechanical_Footprint_File: ftp://fcl.am.freescale.net/ALLEGRO/step/dhvqfn16_0p5_3p6x2p6.STEP; AGILE_PN: 312-81329; CAD_APPROVED: Yes; HEIGHT: 1MM; MFG_NAME01: NEXPERIA; MFG_PN01: 74AVC4TD245BQ,115; ROHS: Yes
U62 = S0T89_3P: IC VREG LDO 3.3V 200mA 1.8-6V SOT89-3; AGILE_PN: 315-81174; CAD_APPROVED: Yes; HEIGHT: 1.6MM; MFG_NAME01: TOREX; ROHS: Yes; Temp Range: -40°C to +85°C
Y4 = XTAL_13: XTAL 16MHZ -- 2520 SMD; AGILE_PN: 230-75774; CAD_APPROVED: Yes; HEIGHT: 0.55MM; MFG_NAME01: NDK; MFG_PN01: NX2520SA-16.000000MHz; ROHS: Yes
J47 = CONN_HDR_12X2: HDR 2X12 TH 2MM CTR 246H AU 110L; AGILE_PN: 210-82753; CAD_APPROVED: Yes; HEIGHT: 6.25MM; MFG_NAME01: ANYTRONIC CORPORATION LIMITED; MFG_PN01: 0912S01 12011N6T-31LF; Package Type: Through Hole; ROHS: Yes; SILK: AUDIO MAIN; Temp Range: -55 °C to 105 °C
J48 = CONN_HDR_5X2: HDR 2X5 TH 2MM CTR 246H AU 110L; AGILE_PN: 210-82754; CAD_APPROVED: Yes; HEIGHT: 6.25MM; MFG_NAME01: ANYTRONIC CORPORATION LIMITED; MFG_PN01: 0912S01 05011N6T-31LF; Package Type: Through Hole; ROHS: Yes; SILK: AUDIO AUX; Temp Range: -55C to +105C
C303 C304 = CAP_NP: CAP CER 1000PF 16V 10% X7R CC0402 ROHS; AGILE_PN: 150-75426; CAD_APPROVED: Yes; FPLIST: CC0402_25,CC0402_HD,0402_CC; HEIGHT: 0.56mm; MFG_NAME01: AVX; MFG_PN01: 0402YC102KAT2A; Package Size: 0402; ROHS: Yes; Tolerance: 10%; VOLTAGE: 16V
C306 C307 = CAP_NP: CAP CER 220PF 50V 10% X7R 0402; AGILE_PN: 150-75829; CAD_APPROVED: Yes; FPLIST: CC0402_25,CC0402_HD,0402_CC; HEIGHT: 0.55MM; MFG_NAME01: KEMET; MFG_PN01: C0402C221K5RAC; ROHS: Yes; Tolerance: 10%; VOLTAGE: 50V
C308 = CAP_NP: CAP CER 4.7uF 6.3V 20% X6S 0402; AGILE_PN: 150-81296; ASSY_OPT: DNP; CAD_APPROVED: Yes; FPLIST: cc0402_tol0p15,cc0402_tol0p15_ov,cc0402_25_tol0p2,0402_cc_nsp; HEIGHT: 0.65MM; MFG_NAME01: MURATA; MFG_PN01: GRM155C80J475MEAA; Package Size: 0402 (1005 Metric); Package Type: SMD/SMT; ROHS: Yes; Rated Voltage: 6.3V; Temp Range: -55°C to +105°C; Tolerance: 20%; VOLTAGE: 6.3V
D28 = BAV99DW: DIODE PWR SW QUAD 215MA 75V SOT363; AGILE_PN: 480-78333; CAD_APPROVED: Yes; HEIGHT: 1.1 MM; MFG_NAME01: DIODES INC; MFG_PN01: BAV99DW-7-F
J49 = CONN_HDR_2X1: HDR 1X2 TH 100MIL SP 339H AU 98L; AGILE_PN: 210-81490; CAD_APPROVED: Yes; HEIGHT: 8.59MM; MFG_NAME01: ANYTRONIC CORPORATION LIMITED; MFG_PN01: 0901S0202011N9T-31RF; ROHS: Yes; SILK: SINC ADC; Temp Range: -55°C to +105°C; Temp_Range: -55°C to +105°C
J50 = CONN_HDR_4X1: HDR 1X4 SMT 2.54MM SP 330H AU; 3D_Mechanical_Footprint_File: ftp://fcl.am.freescale.net/ALLEGRO/step/hdr104_stag_tsm_sm.STEP; AGILE_PN: 211-00001-00; CAD_APPROVED: Yes; HEIGHT: 9.65 MM; MFG_NAME01: SAMTEC; MFG_PN01: TSM-104-01-S-SV; Package Size: SMD-4; Package Type: SMD; ROHS: Yes
L22 = INDUCTOR_FERRITE: IND FER BEAD 120 OHM@100MHZ 0.5A 25% 0402; AGILE_PN: 180-77771; CAD_APPROVED: Yes; FPLIST: IND_0402,0402_CC; HEIGHT: 0.55MM; MFG_NAME01: MURATA; MFG_PN01: BLM15AG121SN1D; PART_TYPE: FERRITE\BEAD; Package Size: 0402; ROHS: Yes; Tolerance: 25%
R768 R769 = RES: RES MF 10.0 OHM 1/16W 1% 0402; AGILE_PN: 470-76090; CAD_APPROVED: Yes; FPLIST: RC0402_25,RC0402_HD,0402_CC; HEIGHT: 0.4MM; MFG_NAME01: BOURNS; MFG_PN01: CR0402-FX-10R0GLF; ROHS: Yes; Tolerance: 1%
R774 R779 = RES: RES MF 4.7K 1/16W 5% 0402; AGILE_PN: 470-75626; ASSY_OPT: DNP; CAD_APPROVED: Yes; FPLIST: RC0402_25,RC0402_HD,0402_CC; HEIGHT: 0.41mm; MFG_NAME01: NIC COMPONENTS CORP; MFG_PN01: NRCL04J472TRF; ROHS: Yes; Tolerance: 5%
R775 R776 = RES: RES MF 75.0K 1/10W 5% AEC-Q200 0402; AGILE_PN: 470-79440; CAD_APPROVED: Yes; FPLIST: RC0402_25,RC0402_HD,0402_CC; HEIGHT: 0.40MM; MFG_NAME01: KOA SPEER; MFG_PN01: RK73B1ETTP753J; ROHS: Yes; Temp Range: -55C to +155C; Tolerance: 5%; VOLTAGE: 50V
R777 R782 R783 R1026 R1027 = RES: RES MF 4.7K 1/16W 5% 0402; AGILE_PN: 470-75626; CAD_APPROVED: Yes; FPLIST: RC0402_25,RC0402_HD,0402_CC; HEIGHT: 0.41mm; MFG_NAME01: NIC COMPONENTS CORP; MFG_PN01: NRCL04J472TRF; ROHS: Yes; Tolerance: 5%
R778 = RES: RES MF 1.50K 1/10W 1% AEC-Q200 0402; AGILE_PN: 470-81990; CAD_APPROVED: Yes; FPLIST: RC0402_25,RC0402_HD,0402_CC; HEIGHT: 0.4 MM; MFG_NAME01: KOA SPEER; MFG_PN01: RK73H1ETTP1501F; ROHS: Yes; Temp Range: -55C to +155C; Tolerance: 1%; VOLTAGE: 50V
TP42-TP44 = TESTLOOP: TEST POINT PAD 036-018MIL TH, NO PART TO ORDER; AGILE_PN: 280-76691; CAD_APPROVED: Yes; HEIGHT: 0.127MM; MFG_NAME01: NA; MFG_PN01: NO PART TO ORDER1; ROHS: Yes
U45 = AMC1106_SOIC8P: IC MODULATOR DELTA-SIGMA 16BIT 3.3-5V SOIC8; 3D_Mechanical_Footprint_File: http://fcl.am.freescale.net/ALLEGRO/step/soic8_1p27_7p6x5p95mm.STEP; AGILE_PN: 315-84369; CAD_APPROVED: Yes; HEIGHT: 2.8MM; MFG_NAME01: TEXAS INSTRUMENTS; Package Size: SOIC8; ROHS: Yes; Temp Range: -40C to +125C
U46 = LSM6DSO_LGA14P: IC 3D ACCELEROMETER GYRO 1.71-3.6V LGA14; AGILE_PN: 312-82731; CAD_APPROVED: Yes; HEIGHT: 0.86MM; MFG_NAME01: ST MICROELECTRONICS; Package Size: LGA-14L; ROHS: Yes; Temp Range: -40°C to 85°C
C312 C464 = CAP_NP: CAP CER 1.0uF 16V 10% X6S 0402; AGILE_PN: 150-80262; CAD_APPROVED: Yes; FPLIST: CC0402_25,CC0402_HD,0402_CC,capc0402_l; HEIGHT: 0.55MM; MFG_NAME01: MURATA; MFG_PN01: GRM155C81C105KE11D; ROHS: Yes; Temp Range: -55°C to +105°C; Tolerance: 10%; VOLTAGE: 16V
D31 = LED: LED GRN SGL 25MA 0603; AGILE_PN: 370-76549; CAD_APPROVED: Yes; HEIGHT: 0.85MM; MFG_NAME01: KINGBRIGHT; MFG_PN01: KPT-1608SGC; ROHS: Yes; SILK: SYNC0
D32 = LED: LED ULTRA BRIGHT RED SGL 30MA 0603; AGILE_PN: 370-75079; CAD_APPROVED: Yes; HEIGHT: 0.9MM; MFG_NAME01: LITE ON; MFG_PN01: LTST-C190KRKT; ROHS: Yes; Rated Voltage: 2V; SILK: SYNC1; Temp Range: -30° C to + 85° C; Temp_Range: -30° C to + 85° C; VOLTAGE: 2V
D33 = LED: LED ULTRA BRIGHT RED SGL 30MA 0603; AGILE_PN: 370-75079; CAD_APPROVED: Yes; HEIGHT: 0.9MM; MFG_NAME01: LITE ON; MFG_PN01: LTST-C190KRKT; ROHS: Yes; Rated Voltage: 2V; SILK: ACT0; Temp Range: -30° C to + 85° C; Temp_Range: -30° C to + 85° C; VOLTAGE: 2V
D35 = LED: LED GRN SGL 25MA 0603; AGILE_PN: 370-76549; CAD_APPROVED: Yes; HEIGHT: 0.85MM; MFG_NAME01: KINGBRIGHT; MFG_PN01: KPT-1608SGC; ROHS: Yes; SILK: ACT1
J51 = CONN_HDR_4X2: CON 2X4 SKT SMT 2.54MM CTR 300H AU; 3D_Mechanical_Footprint_File: ftp://fcl.am.freescale.net/ALLEGRO/step/con_2x4_skt_100_sm.STEP; AGILE_PN: 211-79467; CAD_APPROVED: Yes; HEIGHT: 7.62MM; MFG_NAME01: SAMTEC; ROHS: Yes
J62 J70 = CONN_HDR_8X1: CON 1X8 SKT TH 100MIL SP 344H AU 118L; AGILE_PN: 210-81617; CAD_APPROVED: Yes; HEIGHT: 8.75MM; MFG_NAME01: ANYTRONIC CORPORATION LIMITED; MFG_PN01: 08001S3 0811-29RF; ROHS: Yes; Temp Range: -40°C to +105°C; Temp_Range: -40°C to +105°C
Q19-Q21 Q23 = NPN: TRAN NPN GEN 45V 0.5A SOT-23; AGILE_PN: 480-75158; CAD_APPROVED: Yes; HEIGHT: 1.11 MM; MFG_NAME01: ON SEMICONDUCTOR; ROHS: Yes
R784 R785 R1028 R1032 = RES: RES MF ZERO OHM 1/16W 5% 0402; AGILE_PN: 470-75394; CAD_APPROVED: Yes; FPLIST: RC0402_25,RC0402_HD,RC0402_X2,0402_CC; HEIGHT: 0.45 MM; MFG_NAME01: YAGEO AMERICA; MFG_PN01: RC0402JR-070RL; ROHS: Yes; Tolerance: 5%; VOLTAGE: 1/16W
R875 R878 R885 R891 = RES: RES MF 2.20K 1/10W 1% 0603; AGILE_PN: 470-75806; CAD_APPROVED: Yes; FPLIST: RC0603_OV,RC0603,0603_CC; HEIGHT: 0.55 MM; MFG_NAME01: BOURNS; MFG_PN01: CR0603-FX-2201ELF; ROHS: Yes; Tolerance: 1%
R876 R879 R886 R892 = RES: RES MF 22K 1/16W 5% 0402; AGILE_PN: 470-75609; CAD_APPROVED: Yes; FPLIST: RC0402_25,RC0402_HD,0402_CC; HEIGHT: 0.41mm; MFG_NAME01: SMEC; MFG_PN01: RC73L2Z223JTF; ROHS: Yes; Tolerance: 5%
R877 R880 R887 R893 = RES: RES MF 220 OHM 1/10W 5% 0603; AGILE_PN: 470-30297; CAD_APPROVED: Yes; FPLIST: RC0603_OV,RC0603,0603_CC; HEIGHT: 0.6MM; MFG_NAME01: YAGEO AMERICA; MFG_PN01: RC0603JR-07220RL; ROHS: Yes; Tolerance: 5%
R1029 R1030 = RES: RES MF ZERO OHM 1/16W 5% 0402; AGILE_PN: 470-75394; ASSY_OPT: DNP; CAD_APPROVED: Yes; FPLIST: RC0402_25,RC0402_HD,RC0402_X2,0402_CC; HEIGHT: 0.45 MM; MFG_NAME01: YAGEO AMERICA; MFG_PN01: RC0402JR-070RL; ROHS: Yes; Tolerance: 5%; VOLTAGE: 1/16W
R1031 R1036 R1039 R1040 = RES: RES MF 10K 1/16W 5% 0402; AGILE_PN: 470-75557; ASSY_OPT: DNP; CAD_APPROVED: Yes; FPLIST: RC0402_25,RC0402_HD,0402_CC; HEIGHT: 0.4 MM; MFG_NAME01: VISHAY INTERTECHNOLOGY; MFG_PN01: CRCW040210K0JNED; ROHS: Yes; Tolerance: 5%
R1033-R1035 = RES: RES MF 10K 1/16W 5% 0402; AGILE_PN: 470-75557; CAD_APPROVED: Yes; FPLIST: RC0402_25,RC0402_HD,0402_CC; HEIGHT: 0.4 MM; MFG_NAME01: VISHAY INTERTECHNOLOGY; MFG_PN01: CRCW040210K0JNED; ROHS: Yes; Tolerance: 5%
R1038 = RES: RES MF 100K 1/16W 5% 0402; AGILE_PN: 470-75597; CAD_APPROVED: Yes; FPLIST: RC0402_25,RC0402_HD,0402_CC; HEIGHT: 0.40 MM; MFG_NAME01: VENKEL COMPANY; MFG_PN01: CR0402-16W-104JT; ROHS: Yes; Temp Range: -55C to +155C; Tolerance: 5%; VOLTAGE: 50V
U115 = FXLS8962AF_DFN10: IC ACCELEROMETER 3-AXIS 12BIT 1.71-3.6V AEC-Q100 DFN10; 3D_Mechanical_Footprint_File: ftp://fcl.am.freescale.net/ALLEGRO/step/dfn_10_0p4_2x2.STEP; AGILE_PN: TMP-CIP-7425; CAD_APPROVED: Yes; HEIGHT: 1 MM; MFG_NAME01: NXP SEMICONDUCTORS; PRE_APN: 312-83141; ROHS: Yes; Temp Range: -40  °C to +105 °C

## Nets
5V_SDA_PSW: C365.1 U52.C2(VBUS1) U52.D1(VBUS2) U52.D2(VBUS3) ; also on sheet 5
5V_SYS: C300.1 C301.1 J47.10(B5) J47.12(B6) J70.7 L22.2 ; also on sheet 5 6 14 19 20 27 29
GND: C296.2 C297.2 C298.2 C299.2 C300.2 C301.2 C304.2 C305.2 C308.2 C309.2 C310.2 C311.2 C312.2 C323.2 C324.2 C326.2 C338.2 C346.2 C347.2 C348.2 C349.2 C350.2 C351.2 C352.2 C353.2 C354.2 C355.2 C356.2 C358.2 C359.2 C360.2 C365.2 C370.2 C371.2 C372.2 C373.2 C385.2 C386.2 C387.2 C388.2 C389.2 C390.2 C391.2 C392.2 C393.2 C394.2 C395.2 C397.2 C398.2 C464.2 C465.2 J47.2(B1) J47.6(B3) J47.14(B7) J47.24(B12) J48.2(B1) J48.4(B2) J48.6(B3) J50.4 J51.7(A4) J51.8(B4) J53.5(GND) J56.3(A2) J56.5(A3) J62.8 J70.8 JP2.1 JP3.1 JP4.1 JP5.1 L25.1 Q15.2(SOURCE) Q19.2(EMITTER) Q20.2(EMITTER) Q21.2(EMITTER) Q23.2(EMITTER) R770.2 R779.2 R780.1 R781.1 R811.2 R815.2 R817.2 R821.2 R823.2 R824.2 R825.2 R826.2 R827.2 R828.2 R836.2 R837.2 R839.2 R876.2 R879.2 R886.2 R892.2 R1031.2 R1034.2 R1035.2 SW6.2(SW2) U45.5(DGND) U46.6(GND1) U46.7(GND2) U51.1(GND) U52.B3(GND1) U52.C3(GND2) U52.D3(GND3) U55.B1(USB0_VSS) U55.B5(VSS2) U55.B9(VSS3) U55.B13(VSS4) U55.H1(VREFN) U55.H2(VSSA) U55.J13(XTAL32K_P) U55.M11(VSS_PMU) U55.M12(VSS_DCDC_2) U55.N1(VSS1) U55.N5(USB1_VSS) U55.N12(VSS_DCDC_1) U56.2(GND) U56.5(DIR) U57.2(GND) U58.4(GND) U59.2(GND) U60.6(GND) U61.2(DIR1) U61.8(GND1) U61.10(DIR3) U61.17(NC/GND2) U62.1(GND) U115.10(GND) Y4.2 Y4.4 ; also on sheet 2 5 6 7 8 9 10 11 12 13 14 15 16 17 18 19 20 21 22 27 28 29 30 31
P3V3_SDA: C346.1 C347.1 C348.1 C349.1 C353.1 C354.1 C358.1 C371.1 C373.1 C385.1 C386.1 C388.1 C390.1 C398.1 R808.1 R814.1 R829.2 R830.2 R844.1 R845.1 R851.1 R853.1 R854.1 R861.2 R862.2 R863.2 R864.2 R865.2 R866.2 R1088.1 U55.A3(USB0_3V3) U55.A5(VDD2) U55.A9(VDD3) U55.A13(VDD4) U55.M1(VDD1) U55.M13(VBAT_PMU) U55.N7(USB1_3V3) U55.N13(VBAT_DCDC) U56.1(VCCA) U57.1(VCCA) U58.1(VCCA) U59.1(VCCA) U61.16(VCCB) U62.3(VOUT) ; also on sheet 22
P5V_SDA: C338.1 C359.1 C360.1 C370.1 C372.1 L24.2 R816.1 R850.1 U52.B1(VINT1) U52.B2(VINT2) U52.C1(VINT3) U62.2(VIN)
VCC_I3C: C310.1 C311.1 R771.2 R772.1 R773.2 R774.1 R775.1 R776.1 R777.1 U46.5(VDDIO)
VDD_1V8: C298.1 C299.1 J47.8(B4) ; also on sheet 6 7 8 9 14 16 21 22
DBGIF_DETECT: R840.1 U55.E9(P0_22)
DBGIF_ISP0_CTRL: R841.1 U55.C13(P0_14)
DBGIF_ISP1_CTRL: TP57.1(TP) U55.B8(P1_25) ; also on sheet 22
DBGIF_ISP2_CTRL: TP58.1(TP) U55.E13(P1_26) ; also on sheet 22
DBGIF_ISP3_CTRL: TP59.1(TP) U55.G8(P1_29) ; also on sheet 22
DBGIF_ISP4_CTRL: R822.2 TP60.1(TP) U55.G11(P1_1)
DBGIF_RESET: U55.E6(P0_19) U57.3(A)
DBGIF_RESET_TXEN: R837.1 U55.C12(P0_13) U57.5(DIR)
DBGIF_TCK_SWCLK: U55.L12(P0_0) U58.2(A1)
DBGIF_TDI: U55.F5(P0_1) U58.3(A2)
DBGIF_TDO_SWO: U55.F8(P0_3) U56.3(A)
DBGIF_TMS_SWDIO: U55.B11(P0_2) U59.3(A)
DBGIF_TMS_SWDIO_TXEN: R836.1 U55.F13(P0_28) U59.5(DIR)
DBGIF_VREF: C392.1 R838.2 R839.1 U55.L1(P0_31)
DC_GPIO1: J47.21(A11) ; also on sheet 8
DC_GPIO2: J47.22(B11) ; also on sheet 8
DC_I2S1_MCLK: J47.1(A1) ; also on sheet 8
DC_I2S1_RX_BCLK: J47.5(A3) ; also on sheet 8
DC_I2S1_RX_D0: J47.11(A6) ; also on sheet 8
DC_I2S1_RX_SYNC: J47.9(A5) ; also on sheet 8
DC_I2S1_TX_BCLK: J47.23(A12) ; also on sheet 8
DC_I2S1_TX_D0: J47.17(A9) ; also on sheet 8
DC_I2S1_TX_D1: J47.18(B9) ; also on sheet 8
DC_I2S1_TX_SYNC: J47.16(B8) ; also on sheet 8
DC_I2S4_MCLK: J48.1(A1) ; also on sheet 8
DC_I2S4_RX_BCLK: J48.5(A3) ; also on sheet 8
DC_I2S4_RX_D0: J48.8(B4) ; also on sheet 8
DC_I2S4_RX_SYNC: J48.7(A4) ; also on sheet 8
DC_I2S4_TX_BCLK: J48.3(A2) ; also on sheet 8
DC_I2S4_TX_D0: J48.10(B5) ; also on sheet 8
DC_I2S4_TX_SYNC: J48.9(A5) ; also on sheet 8
DC_INT: J47.3(A2) ; also on sheet 8
DC_RESET: J47.7(A4) ; also on sheet 8
ECAT_ACT0: R885.2 ; also on sheet 16
ECAT_ACT1: R891.2 ; also on sheet 16
ECAT_SYNC0: R875.2 ; also on sheet 16
ECAT_SYNC1: R878.2 ; also on sheet 16
GPIO_AD_06: J70.1 ; also on sheet 8 27
GPIO_AD_08: J62.1 ; also on sheet 8 27
GPIO_AD_15: J70.2 ; also on sheet 8 27
GPIO_AD_18: J70.5 ; also on sheet 8 27
GPIO_AD_19: J70.6 ; also on sheet 8 27
GPIO_AON_08: J70.4 ; also on sheet 8 27
GPIO_AON_09: J70.3 ; also on sheet 8 27
GPIO_SD_B1_00: J62.3 ; also on sheet 8 10 27
GPIO_SD_B1_01: J62.4 ; also on sheet 8 10 27
GPIO_SD_B1_02: J62.6 ; also on sheet 8 10 27
GPIO_SD_B1_03: J62.5 ; also on sheet 8 10 27
HW_VER_0: R828.1 R862.1 U55.E8(P1_27)
HW_VER_1: R827.1 R863.1 U55.A8(P1_28)
HW_VER_2: R826.1 R864.1 U55.F9(P1_30)
HW_VER_3: R825.1 R861.1 U55.B2(P1_4)
HW_VER_4: R824.1 R866.1 U55.M5(P1_5)
HW_VER_5: R823.1 R865.1 U55.H5(P1_6)
HW_VER_6: JP2.2 Q15.1(GATE) R829.1 U55.H9(P0_18)
HW_VER_7: JP4.2 R830.1 U55.N2(P0_27) U58.5(DIR)
I3C2_PUR: J50.3 R778.1 ; also on sheet 8
I3C2_SCL: J47.13(A7) J50.1 R776.2 R783.2 R784.1 U46.13(SCL) ; also on sheet 8 31
I3C2_SDA: J47.15(A8) J50.2 R775.2 R778.2 R782.2 R785.1 U46.14(SDA) ; also on sheet 8 31
IF_DETECT: J56.9(A5) R840.2
IF_ISPEN: J56.7(A4) R841.2
IF_RST: J56.10(B5) R835.2 U60.7(3Y1)
IF_SWCLK: J56.4(B2) R831.2 U60.3(2Y1)
IF_SWDIO: J56.2(B1) R833.2 U60.15(1Y1)
IF_TDI: J56.8(B4) R832.2
IF_TDO_SWO: J56.6(B3) R834.2 U60.11(4Y1)
INT1_COMBO: R1029.2 R1039.2 ; also on sheet 8
INT2_COMBO: R1030.2 R1040.2 ; also on sheet 8
JTAG_TCK: U60.4(2Z) ; also on sheet 8 27
JTAG_TDO: U60.12(4Z) ; also on sheet 8 27
JTAG_TMS: U60.16(1Z) ; also on sheet 8 27
LED_HEARTBEAT: TP46.1(Pin1) U55.C7(P1_16)
LED_OPT1: TP47.1(Pin1) U55.J9(P1_17)
LED_OPT2: TP48.1(Pin1) U55.G9(P1_18)
LED_SWO_ACT: TP45.1(Pin1) U55.B3(P1_13)
LED_USB_COMM: D29.C(CATHODE) U55.F12(P1_12)
LED_VCOM_ACT: D30.C(CATHODE) U55.B6(P1_15)
LPI2C2_SCL: R1027.2 R1028.1 ; also on sheet 8 14 21 29
LPI2C2_SDA: R1026.2 R1032.2 ; also on sheet 8 14 21 29
LPUART1_RXD: R848.1 ; also on sheet 8
LPUART1_TXD: R1076.1 ; also on sheet 8
LPUART12_RXD: R1077.1 ; also on sheet 2 8
LPUART12_TXD: R1078.1 ; also on sheet 2 8
MCU_POWER_EN: R818.1 U55.M2(P0_8)
PIO0_5-ISP_EN-LED_SWD_ACT: D39.C(CATHODE) JP3.2 R851.2 U55.A7(P0_5)
RST_TGTMCU_B: J62.2 ; also on sheet 6 22 27
SENSOR_3V3: C296.1 C297.1 C304.1 C305.1 C312.1 C464.1 C465.1 J47.4(B2) J51.1(A1) J51.2(B1) J62.7 JP6.1 R772.2 R782.1 R783.1 R877.1 R880.1 R887.1 R893.1 R1026.1 R1027.1 R1033.1 R1036.1 R1038.1 R1039.1 R1040.1 U45.8(DVDD) U115.1(VDD) ; also on sheet 2 5 6 7 8 9 10 11 12 13 14 15 16 17 18 19 20 21 22 27 28 29 30 31
SINC2_EMBIT: U45.6(DOUT) ; also on sheet 8
SINC2_EMCLK: U45.7(CLKIN) ; also on sheet 8
SINC2_MOD_CLK: TP41.1(TP) ; also on sheet 8
SINC_AGND: C303.2 C306.2 C307.2 C400.2 D28.1(A1) D28.4(A2) R770.1 U45.4(AGND)
SINC_VDDA_5V: C303.1 C400.1 D28.2(C1) D28.5(C2) L22.1 U45.1(AVDD)
TRG_FC0_RXD: R847.2 U55.E12(P0_24)
TRG_FC0_TXD: R846.2 U55.A11(P0_25)
TRG_FC1_RXD: R1075.2 U55.J7(P1_10)
TRG_FC1_TXD: R1074.2 U55.G6(P1_11)
TRG_RST: U60.8(3Z) ; also on sheet 22
U_GPIO_0: R822.1 TP61.1(TP)
U_GPIO_1: TP53.1(TP) U55.C1(P1_9)
U_GPIO_2: TP54.1(TP) U55.H6(P1_31)
U_GPIO_3: TP55.1(TP) U55.M7(P1_21)
U_GPIO_4: R852.1 TP56.1(TP) U55.C2(P1_20)
U_GPIO_5: TP62.1(TP) U55.J5(P1_7)
V_TGTMCU: C387.1 C389.1 C391.1 C393.1 C394.1 C395.1 C397.1 J56.1(A1) JP6.2 R838.1 R842.2 R849.1 R901.1 R902.1 R903.1 U56.6(VCCB) U57.6(VCCB) U58.8(VCCB) U59.6(VCCB) U60.14(VCC) U61.1(VCCA) U61.7(DIR4) U61.15(DIR2) ; also on sheet 22
VREF: C351.1 R845.2 U55.G1(VREFP) U55.H13(P1_19)
VTRG_FAULT_B: R814.2 R852.2 U52.A2(~{FAULT})
XTAL32M_N: C323.1 U55.M3(XTAL32M_N) Y4.3
XTAL32M_P: C324.1 U55.N3(XTAL32M_P) Y4.1
N103834887: J51.3(A2) J51.4(B2) R784.2
N103834897: J51.5(A3) J51.6(B3) R785.2
N103909102: C308.1 C309.1 R771.1 U46.8(VDD)
N103909121: R777.2 U46.12(CS)
N103909127: R774.2 R779.1 U46.1(SDO/SA0)
N103909137: R773.1 U46.4(INT1)
N103909149: TP42.1(Pin1) U46.11(SDO_AUX)
N103909150: TP43.1(Pin1) U46.10(OCS_AUX)
N103909151: TP44.1(Pin1) U46.9(INT2)
N103909152: R780.2 U46.2(SDX)
N103909154: R781.2 U46.3(SCX)
N103911488: D28.6(AC1) J49.1 R768.1
N103911494: D28.3(AC2) J49.2 R769.1
N103911836: C307.1 R768.2 U45.2(AINP)
N103911844: C306.1 R769.2 U45.3(AINN)
N103961253: R812.2 U55.N6(USB1_DM)
N103961260: R813.2 U55.M6(USB1_DP)
N103961264: R811.1 R850.2 U55.N8(USB1_VBUS)
N103961315: C326.1 R808.2 R809.1 U55.J6(RESETN)
N103961319: C352.1 C355.1 C356.1 L23.2 U55.M9(VDD_PMU) U55.N9(FB)
N103961455: L23.1 U55.N11(LX)
N103961642: R809.2 SW6.1(SW1)
N103961796: C350.1 R844.2 U55.G2(VDDA)
N103962355: J53.6(SHELL1) J53.7(SHELL2) J53.8(SHELL3) J53.9(SHELL4) L25.2
N103962365: J53.1(VBUS) L24.1 U51.4(VCC)
N103962432: J53.2(D-) R812.1 U51.3(I/O2)
N103962456: J53.3(D+) R813.1 U51.2(I/O1)
N103962999: R815.1 U52.A3(ILIM)
N103963079: R816.2 R817.1 R818.2 U52.A1(EN)
N104012170: JP7.2 R821.1
N104016532: R831.1 U58.7(B1)
N104016534: R832.1 U58.6(B2)
N104016623: R835.1 R902.2 U57.4(B)
N104016749: R833.1 R903.2 U59.4(B)
N104016751: R834.1 R901.2 U56.4(B)
N104017363: JP5.2 R842.1 U60.2(S)
N104034773: R846.1 U61.14(B1)
N104034775: R847.1 U61.13(B2)
N104034777: R848.2 U61.3(A1)
N104034811: Q15.3(DRAIN) R849.2 U61.9(~{OE})
N104034835: R1078.2 U61.6(A4)
N104105294: D30.A(ANODE) R854.2
N104105296: D29.A(ANODE) R853.2
N104599012: D31.C(CATHODE) Q19.3(COLLECTOR)
N104599036: Q19.1(BASE) R875.1 R876.1
N104599080: D32.C(CATHODE) Q20.3(COLLECTOR)
N104599094: Q20.1(BASE) R878.1 R879.1
N104600982: D33.C(CATHODE) Q21.3(COLLECTOR)
N104600995: Q21.1(BASE) R885.1 R886.1
N104601399: D35.C(CATHODE) Q23.3(COLLECTOR)
N104601413: Q23.1(BASE) R891.1 R892.1
N105070687: R1028.2 U115.5(SCL/SCLK)
N105070691: R1033.2 U115.7(~{SPI_CS}/WAKE_UP)
N105070693: R1034.1 U115.9(INTF_SEL)
N105070700: R1035.1 R1036.2 U115.2(BT_MODE)
N105070744: R1029.1 U115.8(INT1/MOT_DET)
N105070750: R1030.1 U115.6(INT2/EXT_TRIG/BOOT_OUT)
N105070826: R1031.1 R1038.2 U115.3(SA0/SPI_MISO)
N105070844: R1032.1 U115.4(SDA/SPI_MOSI/SPI_DATA)
N105256205: R1074.1 U61.12(B3)
N105256208: R1075.1 U61.11(B4)
N105257045: R1076.2 U61.4(A2)
N105257114: R1077.2 U61.5(A3)
N105291076: JP7.1 U55.L13(P0_9)
N105373803: D39.A(ANODE) R1088.2
N107441452: D33.A(ANODE) R887.2
N107441453: D31.A(ANODE) R877.2
N107441454: D35.A(ANODE) R893.2
N107441456: D32.A(ANODE) R880.2

Not connected (* = marked no-connect by the designer): J47 19(A10) 20(B10); J53 4(ID)*; U55 A1(USB_DM)* A2(USB_DP)* A6(P1_8)* A12(P0_21)* B7(P0_6)* B12(P0_20)* E1(P1_0)* E2(P0_12)* E5(P0_30)* E7(P0_4)* F1(P0_11)* F2(P0_10)* F6(P1_24)* G3(P0_17)* G5(P0_7)* G12(P1_2)* G13(P1_3)* H8(P0_29)* H12(P0_26)* J1(P0_23)* J2(P0_16)* J8(P1_23)* J12(XTAL32K_N)* L2(P0_15)* L7(P1_14)* M8(P1_22)*; U60 1(1Y0)* 5(2Y0)* 9(3Y0)* 10(NC)* 13(4Y0)*

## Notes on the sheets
sheet 23
- MCU Power and USB
- RESET
- Items
- Description
- OB setting
- HW_VER_0(PIO1_27)
- Power negotiation when low
- 0
- HW_VER_1(PIO1_28)
- Reserved
- 1
- Default: OPEN
- HW_VER_2(PIO1_30)
- USBSIO bridge disabled / not present when 0
- 0
- HW_VER_3(PIO1_4)
- OB (0) / Pro (1) type select
- 0
- HW_VER_4(PIO1_5)
- Board identity code used (when low)
- 0
- HW_VER_5(PIO1_6)
- Power measurement enabled/present when low
- 1
- HW_VER_6(PIO0_18)
- VCOM disabled when low
- 1
- HW_VER_7(PIO0_27)
- SWD debug disabled when low
- 1
- ISP ENABLE
- Default: Open
- MAX 200mA
- Debug Interface
- Default: Open
- MICRO USB
- Default: 1-2
- JP5(OPEN,Default) ->RT Debugger
  JP5(SHORT) ->External J56 Debugger
- LED1: USB communication
- LED3: Status activity
- LED4: VCOM activity
sheet 24
- AUDIO MAIN CONN
- DC_SAI1_MCLK
- DC_INT
- DC_SAI1_RX_BCLK
- DC_3V3(Opt)
- DC_RESET
- DC_1V8(Opt)
- DC_SAI1_RX_SYNC
- DC_SAI1_RXD0
- DC_5V
- DC_I2C_SCL
- DC_I2C_SDA
- DC_SAI1_TX_SYNC
- DC_I2S1_TX_D0
- DC_I2S1_TX_D2
- DC_I2S1_TX_D1
- DC_I2S1_TX_D3
- DC_GPIO1
- DC_GPIO2
- DC_SAI1_TX_BCLK
- AUDIO AUX CONN
- If Audio aux conn (J48) is used, please mount resistors below,
  R125,R127,R129,R131,R132,R133,R134
- DC_I2S2_MCLK
- DC_I2S2_TX_BCLK
- DC_I2S2_RX_BCLK
- DC_I2S2_RX_SYNC
- DC_I2S2_TX_SYNC
- DC_I2S2_RX_D0
- DC_I2S2_TX_D0
sheet 25
- SINC ADC
- Input range:
  -320mV ~ +320mV
- Differential pair laout.
- Default: OPEN
- Analog GND plane
  is required.
- I3C GYRO&ACCELEROMETER
sheet 26
- Accelerometer
- I2C CONN Extension
- I2C ADDRESS:  WR:32 RD:33
- USER LED3
- USER LED4
- USER LED5
- USER LED6
- Mikroe Click Connectors
- (Signals are shared with Arduino.)
- AN
- RST
- INT
- PWM
- CS
- RX
- SCK
- TX
- MISO
- SCL
- MOSI
- SDA
- +3.3V
- +5V
- GND
- GND
